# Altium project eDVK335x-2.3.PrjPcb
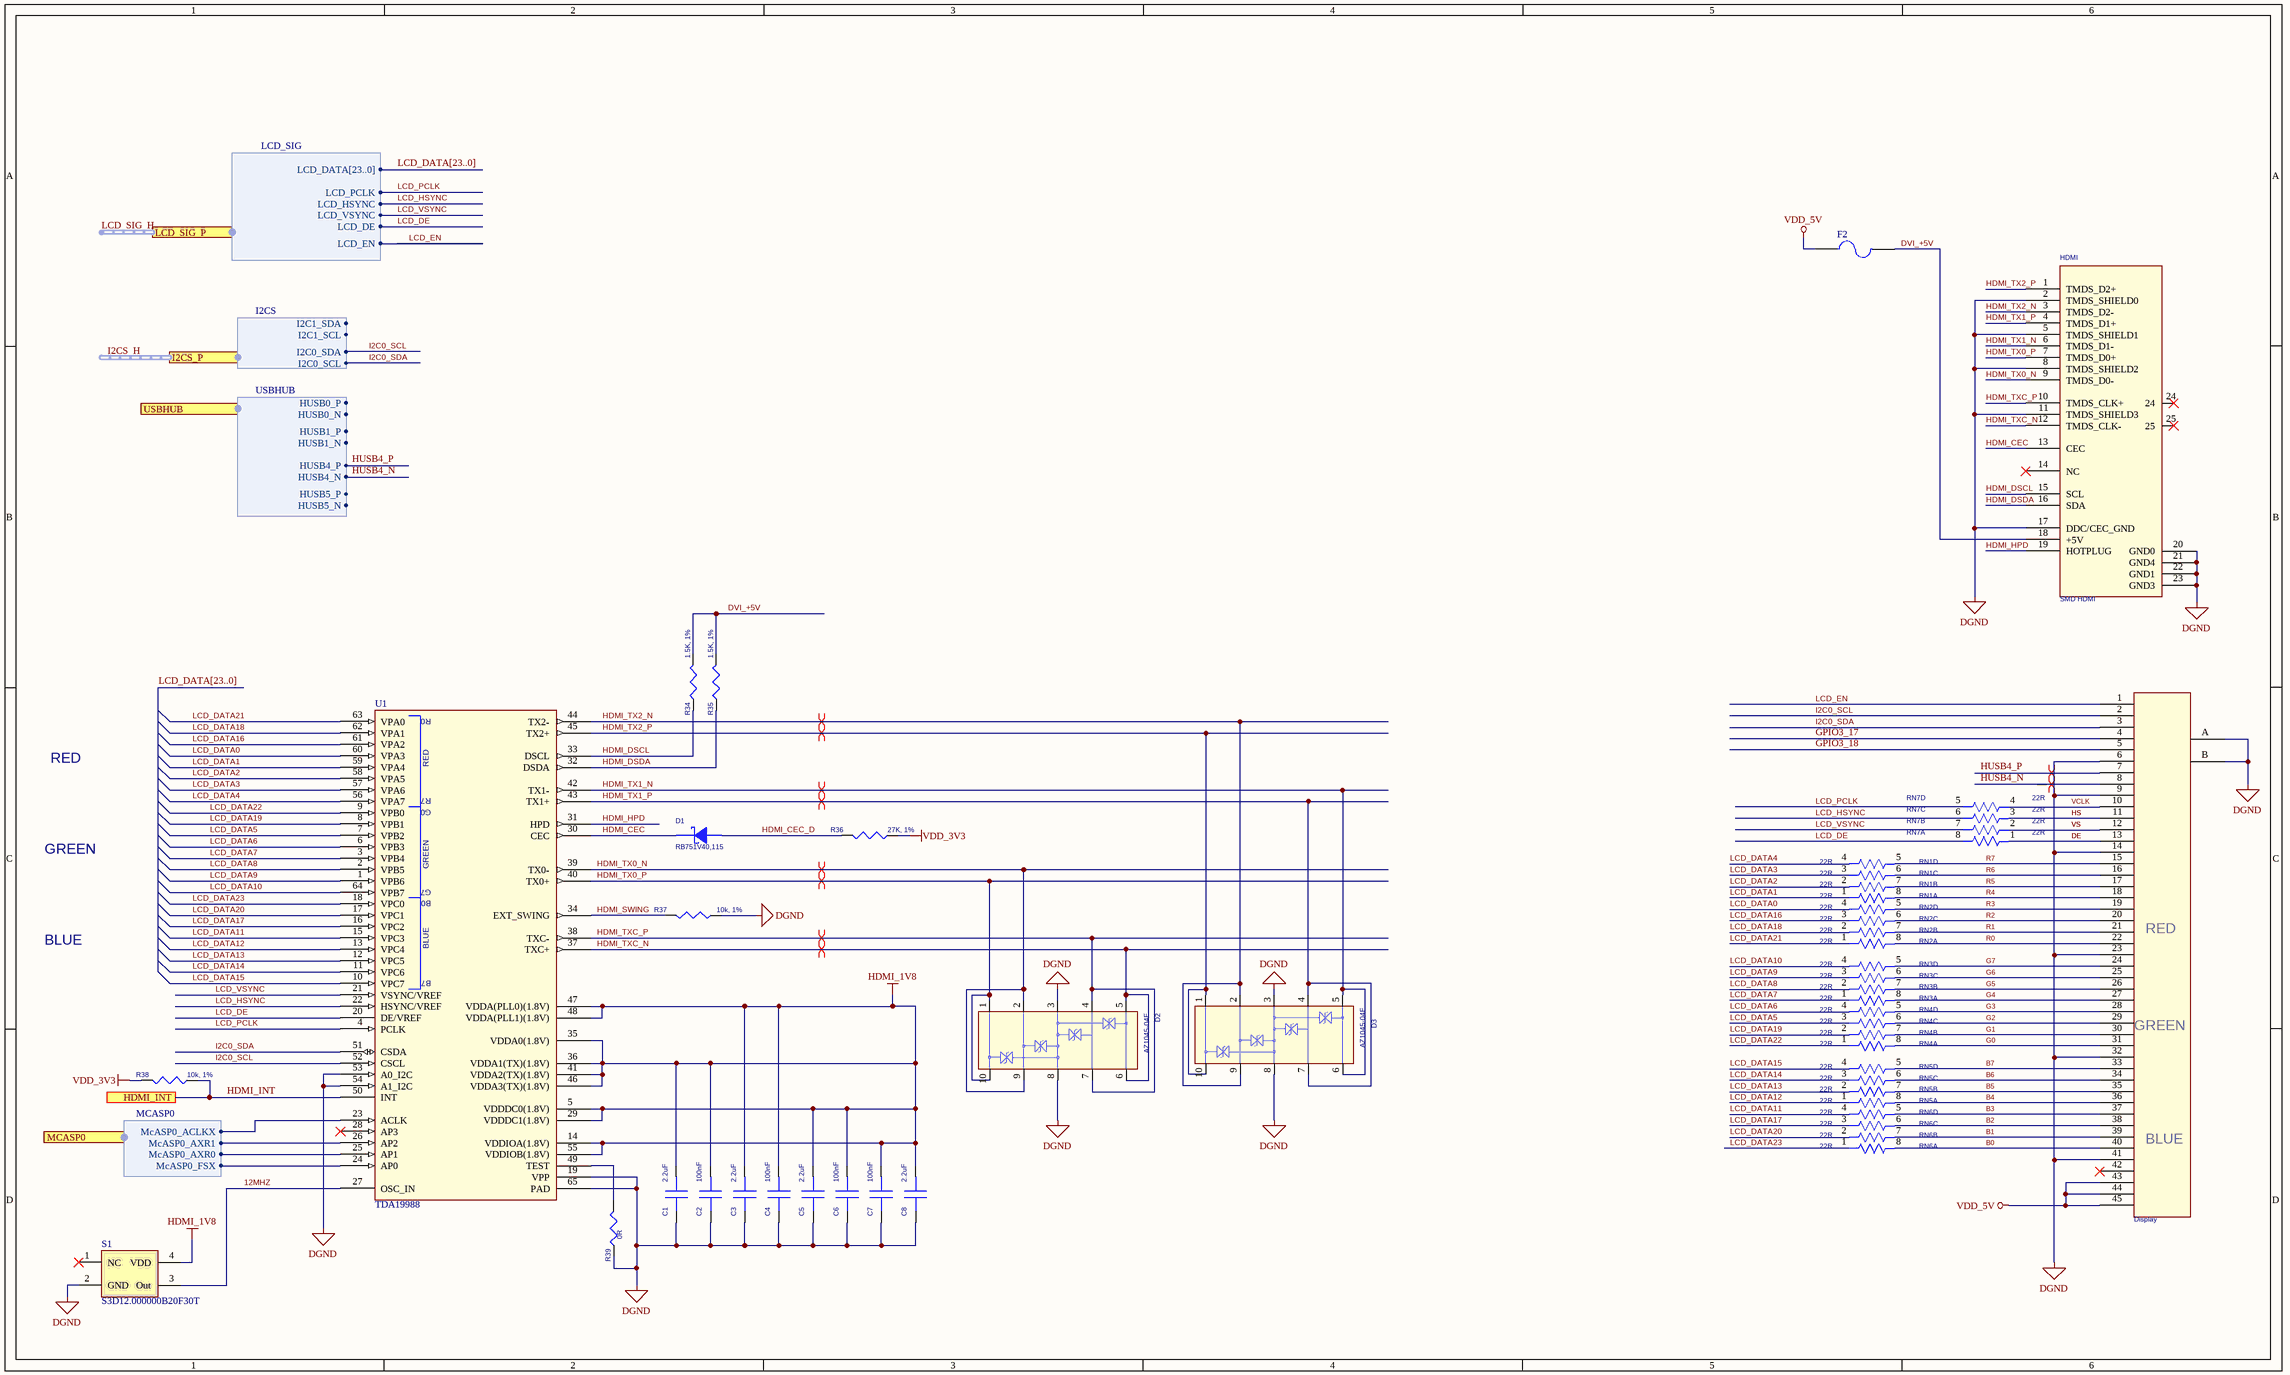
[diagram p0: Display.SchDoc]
13 sheets, 247 parts. Net scope: global (net labels, ports and power ports of the same name join across sheets).
Board file: eDVK335X-2.3.2.PcbDoc
Sheets:
  Display.SchDoc
  SODIMM-2.SchDoc
  mPCIUSB.SchDoc
  Eth.SchDoc
  Power.SchDoc
  SDCard.SchDoc
  Sound.SchDoc
  Config.SchDoc
  USBHUB2.SchDoc
  UARTS.SchDoc
  Others.SchDoc
  eMod-Wifi.SchDoc
  CAN.SchDoc

## Sheet Display.SchDoc
size 508 x 304 mm

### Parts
C1  2.2uF  [C0603]
C2  100nF  [C0603]
C3  2.2uF  [C0603]
C4  100nF  [C0603]
C5  2.2uF  [C0603]
C6  100nF  [C0603]
C7  100nF  [C0603]
C8  2.2uF  [C0603]
D1  RB751V40,115  [SOD323]
D2  AZ1045-04F  [DFN2510P10E]
D3  AZ1045-04F  [DFN2510P10E]
Display  FPC - 45  [con-fpc-p05-45p]  (value not drawn)
F2  Fuse 1A  [F1206]  (value not drawn)
HDMI  SMD HDMI  [HDMI0119-20-RM-A-SMD]
R34  1.5K, 1%  [R0603]
R35  1.5K, 1%  [R0603]
R36  27K, 1%  [R0603]
R37  10k, 1%  [R0603]
R38  10k, 1%  [R0603]
R39  0R  [R0603]
RN1  22R  [rn-8p4r-0603]  (parts A,B,C,D of 4)
RN2  22R  [rn-8p4r-0603]  (parts A,B,C,D of 4)
RN3  22R  [rn-8p4r-0603]  (parts A,B,C,D of 4)
RN4  22R  [rn-8p4r-0603]  (parts A,B,C,D of 4)
RN5  22R  [rn-8p4r-0603]  (parts A,B,C,D of 4)
RN6  22R  [rn-8p4r-0603]  (parts A,B,C,D of 4)
RN7  22R  [rn-8p4r-0603]  (parts A,B,C,D of 4)
S1  S3D12.000000B20F30T  [OSCSC250P320X250X100-4N-2]
U1  TDA19988  [QFN64S9X9P5]

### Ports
HDMI_INT, I2CS_P (harness I2CS), LCD_SIG_P (harness LCD_SIG), MCASP0 (harness MCASP0), USBHUB (harness USBHUB)

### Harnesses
MCASP0: McASP0_ACLKX, McASP0_FSX, McASP0_AXR0, McASP0_AXR1
LCD_SIG: LCD_DATA[23..0], LCD_PCLK, LCD_HSYNC, LCD_VSYNC, LCD_DE, LCD_EN
I2CS: I2C0_SDA, I2C0_SCL, I2C1_SDA, I2C1_SCL
USBHUB: HUSB0_P, HUSB0_N, HUSB1_P, HUSB1_N, HUSB4_P, HUSB4_N, HUSB5_P, HUSB5_N

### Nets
DGND: C1.2 C2.2 C3.2 C4.2 C5.2 C6.2 C7.2 C8.2 D2.3 D2.8 D3.3 D3.8 Display.6(VD3) Display.9(VD6) Display.14(VD10) Display.23(VD18) Display.32(nRESET) Display.41(NC4) Display.A Display.B HDMI.2(TMDS_SHIELD0) HDMI.5(TMDS_SHIELD1) HDMI.8(TMDS_SHIELD2) HDMI.11(TMDS_SHIELD3) HDMI.17(DDC/CEC_GND) HDMI.20(GND0) HDMI.21(GND4) HDMI.22(GND1) HDMI.23(GND3) R37.2(P2) R39.2(P2) S1.2(GND) U1.19(VPP) U1.53(A0_I2C) U1.54(A1_I2C) U1.65(PAD)
HDMI_1V8: C1.1 C2.1 C3.1 C4.1 C5.1 C6.1 C7.1 C8.1 S1.4(VDD) U1.5(VDDDC0(1.8V)) U1.14(VDDIOA(1.8V)) U1.29(VDDDC1(1.8V)) U1.35(VDDA0(1.8V)) U1.36(VDDA1(TX)(1.8V)) U1.41(VDDA2(TX)(1.8V)) U1.46(VDDA3(TX)(1.8V)) U1.47(VDDA(PLL0)(1.8V)) U1.48(VDDA(PLL1)(1.8V)) U1.55(VDDIOB(1.8V))
VDD_3V3: R36.2(P2) R38.1(P1)
VDD_5V: Display.43(NC3) Display.44(NC4) Display.45(NC4) F2.2
12MHZ: S1.3(Out) U1.27(OSC_IN)
B0: Display.40(NC4) RN6.8
B1: Display.39(NC3) RN6.7
B2: Display.38(NC2) RN6.6
B3: Display.37(NC1) RN6.5
B4: Display.36(VCLK) RN5.8
B5: Display.35(HSYNC) RN5.7
B6: Display.34(VSYNC) RN5.6
B7: Display.33(VDEN) RN5.5
DE: Display.13(VD9) RN7.1
DVI_+5V: F2.1 HDMI.18(+5V) R34.1(P1) R35.1(P1)
G0: Display.31(EINT10) RN4.8
G1: Display.30(TOUT1) RN4.7
G2: Display.29(GND3) RN4.6
G3: Display.28(VD23) RN4.5
G4: Display.27(VD22) RN3.8
G5: Display.26(VD21) RN3.7
G6: Display.25(VD20) RN3.6
G7: Display.24(VD19) RN3.5
GPIO3_17: Display.4(VD1)
GPIO3_18: Display.5(VD2)
HDMI_CEC: D1.1(C) HDMI.13(CEC) U1.30(CEC)
HDMI_CEC_D: D1.2(A) R36.1(P1)
HDMI_DSCL: HDMI.15(SCL) R34.2(P2) U1.33(DSCL)
HDMI_DSDA: HDMI.16(SDA) R35.2(P2) U1.32(DSDA)
HDMI_HPD: HDMI.19(HOTPLUG) U1.31(HPD)
HDMI_INT: R38.2(P2) U1.50(INT) ; port HDMI_INT
HDMI_SWING: R37.1(P1) U1.34(EXT_SWING)
HDMI_TX0_N: D2.2 D2.9 HDMI.9(TMDS_D0-) U1.39(TX0-)
HDMI_TX0_P: D2.1 D2.10 HDMI.7(TMDS_D0+) U1.40(TX0+)
HDMI_TX1_N: D3.5 D3.6 HDMI.6(TMDS_D1-) U1.42(TX1-)
HDMI_TX1_P: D3.4 D3.7 HDMI.4(TMDS_D1+) U1.43(TX1+)
HDMI_TX2_N: D3.2 D3.9 HDMI.3(TMDS_D2-) U1.44(TX2-)
HDMI_TX2_P: D3.1 D3.10 HDMI.1(TMDS_D2+) U1.45(TX2+)
HDMI_TXC_N: D2.5 D2.6 HDMI.12(TMDS_CLK-) U1.37(TXC+)
HDMI_TXC_P: D2.4 D2.7 HDMI.10(TMDS_CLK+) U1.38(TXC-)
HS: Display.11(GND1) RN7.3
HUSB4_N: Display.8(VD5) ; port USBHUB.HUSB4_N
HUSB4_P: Display.7(VD4) ; port USBHUB.HUSB4_P
I2C0_SCL: Display.2(VDD5V_2) Display.3(VD0) U1.51(CSDA) U1.52(CSCL) ; port I2CS_P.I2C0_SDA, port I2CS_P.I2C0_SCL  [also labelled I2C0_SDA]
LCD_DATA0: RN2.4 U1.60(VPA3)
LCD_DATA1: RN1.1 U1.59(VPA4)
LCD_DATA2: RN1.2 U1.58(VPA5)
LCD_DATA3: RN1.3 U1.57(VPA6)
LCD_DATA4: RN1.4 U1.56(VPA7)
LCD_DATA5: RN4.3 U1.7(VPB2)
LCD_DATA6: RN4.4 U1.6(VPB3)
LCD_DATA7: RN3.1 U1.3(VPB4)
LCD_DATA8: RN3.2 U1.2(VPB5)
LCD_DATA9: RN3.3 U1.1(VPB6)
LCD_DATA10: RN3.4 U1.64(VPB7)
LCD_DATA11: RN6.4 U1.15(VPC3)
LCD_DATA12: RN5.1 U1.13(VPC4)
LCD_DATA13: RN5.2 U1.12(VPC5)
LCD_DATA14: RN5.3 U1.11(VPC6)
LCD_DATA15: RN5.4 U1.10(VPC7)
LCD_DATA16: RN2.3 U1.61(VPA2)
LCD_DATA17: RN6.3 U1.16(VPC2)
LCD_DATA18: RN2.2 U1.62(VPA1)
LCD_DATA19: RN4.2 U1.8(VPB1)
LCD_DATA20: RN6.2 U1.17(VPC1)
LCD_DATA21: RN2.1 U1.63(VPA0)
LCD_DATA22: RN4.1 U1.9(VPB0)
LCD_DATA23: RN6.1 U1.18(VPC0)
LCD_DE: RN7.8 U1.20(DE/VREF) ; port LCD_SIG_P.LCD_DE
LCD_EN: Display.1(VDD5V_1) ; port LCD_SIG_P.LCD_EN
LCD_HSYNC: RN7.6 U1.22(HSYNC/VREF) ; port LCD_SIG_P.LCD_HSYNC
LCD_PCLK: RN7.5 U1.4(PCLK) ; port LCD_SIG_P.LCD_PCLK
LCD_VSYNC: RN7.7 U1.21(VSYNC/VREF) ; port LCD_SIG_P.LCD_VSYNC  [project net LCD_SIG_H.LCD_VSYNC]
McASP0_ACLKX: U1.23(ACLK) ; port MCASP0.McASP0_ACLKX
McASP0_AXR0: U1.25(AP1) ; port MCASP0.McASP0_AXR0
McASP0_AXR1: U1.26(AP2) ; port MCASP0.McASP0_AXR1
McASP0_FSX: U1.24(AP0) ; port MCASP0.McASP0_FSX
R0: Display.22(VD17) RN2.8
R1: Display.21(VD16) RN2.7
R2: Display.20(GND2) RN2.6
R3: Display.19(VD15) RN2.5
R4: Display.18(VD14) RN1.8
R5: Display.17(VD13) RN1.7
R6: Display.16(VD12) RN1.6
R7: Display.15(VD11) RN1.5
VCLK: Display.10(VD7) RN7.4
VS: Display.12(VD8) RN7.2
NetR39_1: R39.1(P1) U1.49(TEST)

Not connected (* = marked no-connect by the designer): Display 42(NC2)*; HDMI 14(NC)* 24* 25*; S1 1(NC)*; U1 28(AP3)*

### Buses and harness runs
bus LCD_DATA[23..0]
harness I2CS_H = port I2CS_P
harness LCD_SIG_H = port LCD_SIG_P

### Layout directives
differential pair: HDMI_TX0_N, HDMI_TX0_P, HDMI_TX1_N, HDMI_TX1_P, HDMI_TX2_N, HDMI_TX2_P, HDMI_TXC_N, HDMI_TXC_P, HUSB4_N, HUSB4_P

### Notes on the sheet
- RED
- GREEN
- (near Display) RED
- BLUE
- (near Display) GREEN
- (near Display) BLUE

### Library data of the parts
C1 C3 C5 C8 = CAP SMD: CAP CER 2.2UF 6.3V 10% X5R 0402; Manufacturer: TDK Corporation; Manufacturer Part Number: C1005X5R0J225K050BC; Capacitance: 2.2µF
C2 C4 C6 C7 = CAP SMD: CAP CER 0.1UF 6.3V 10% X5R 0402; Manufacturer: TDK Corporation; Manufacturer Part Number: C1005X5R0J104K050BA; Capacitance: 0.1µF
D1 = Zener: DIODE SCHOTTKY 40V 120MA SOD323; Manufacturer: NXP Semiconductors; Current - Average Rectified (Io): 120mA (DC); Voltage - Forward (Vf) (Max) @ If: 370mV @ 1mA; Speed: Small Signal =< 200mA (Io), Any Speed; Current - Reverse Leakage @ Vr: 500nA @ 30V; Capacitance @ Vr, F: 2pF @ 1V, 1MHz
D2 D3 = TVS Arrays_1
Display = LCD-888_0: FPC, 45pin, 0.5mm pitch, Bottom Contact, Flip Lock
F2 = Fuse 2: Fuse 1A (1206)
HDMI = HDMI_2
R34 R35 = RES SMD: Manufacturer: Yageo; Manufacturer Part Number: RC0402FR-071K5L; Power (Watts): 0.063W, 1/16W; Temperature Coefficient: ±100ppm/°C
R36 = RES SMD: RES 27.0K OHM 1/16W 1% 0402 SMD; Manufacturer: Yageo; Manufacturer Part Number: RC0402FR-0727KL; Power (Watts): 0.063W, 1/16W; Temperature Coefficient: ±100ppm/°C
R37 R38 = RES SMD: RES 10K OHM 1/16W 5% 0402 SMD; Manufacturer: Rohm Semiconductor; Manufacturer Part Number: MCR01MZPJ103; Power (Watts): 0.063W, 1/16W; Temperature Coefficient: ±200ppm/°C
R39 = RES SMD: Manufacturer: Yageo; Manufacturer Part Number: RC0402JR-070RL; Resistance (Ohms): 0.0; Power (Watts): 0.063W, 1/16W; Tolerance: Jumper
RN1-RN7 = R_PAK4: ?; OriginalSymbolOrigin: (-100,50)
S1 = ABM8G_1: OSC; SMD; 4 Leads; Body 3.2 x 2.5  P.N: S3D24.576000D20F30T; Manufacturer: TXC; Manufacturer PN: 7V; Designator: ABM8G
U1 = TDA19988: IC HDMI TRANSMITTER 64-HVQFN; Manufacturer: NXP Semiconductors; Manufacturer Part Number: TDA19988AHN/C1,551

## Sheet SODIMM-2.SchDoc
size A2
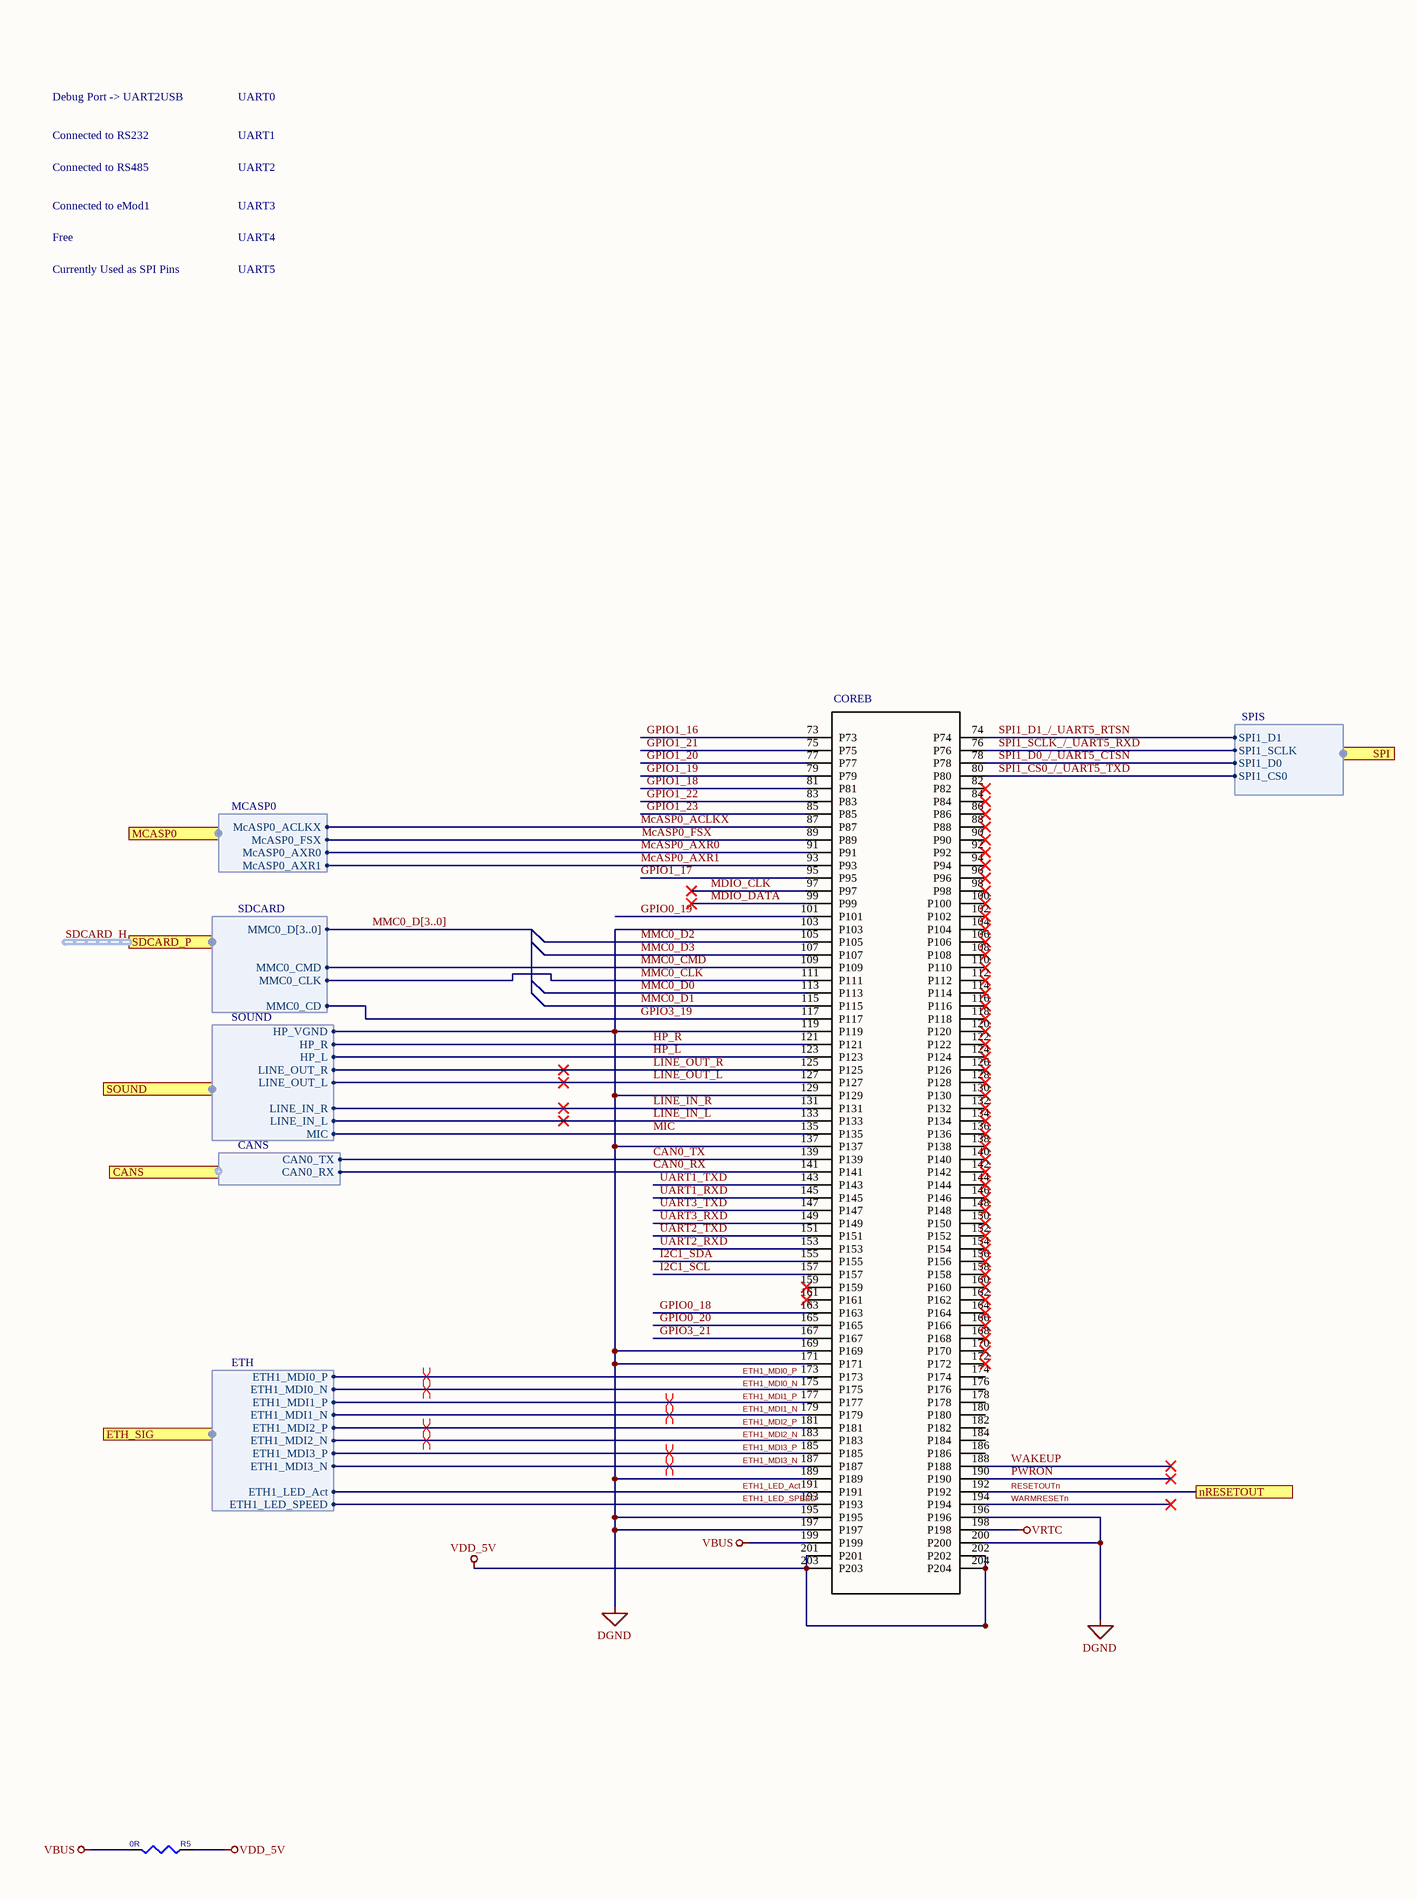
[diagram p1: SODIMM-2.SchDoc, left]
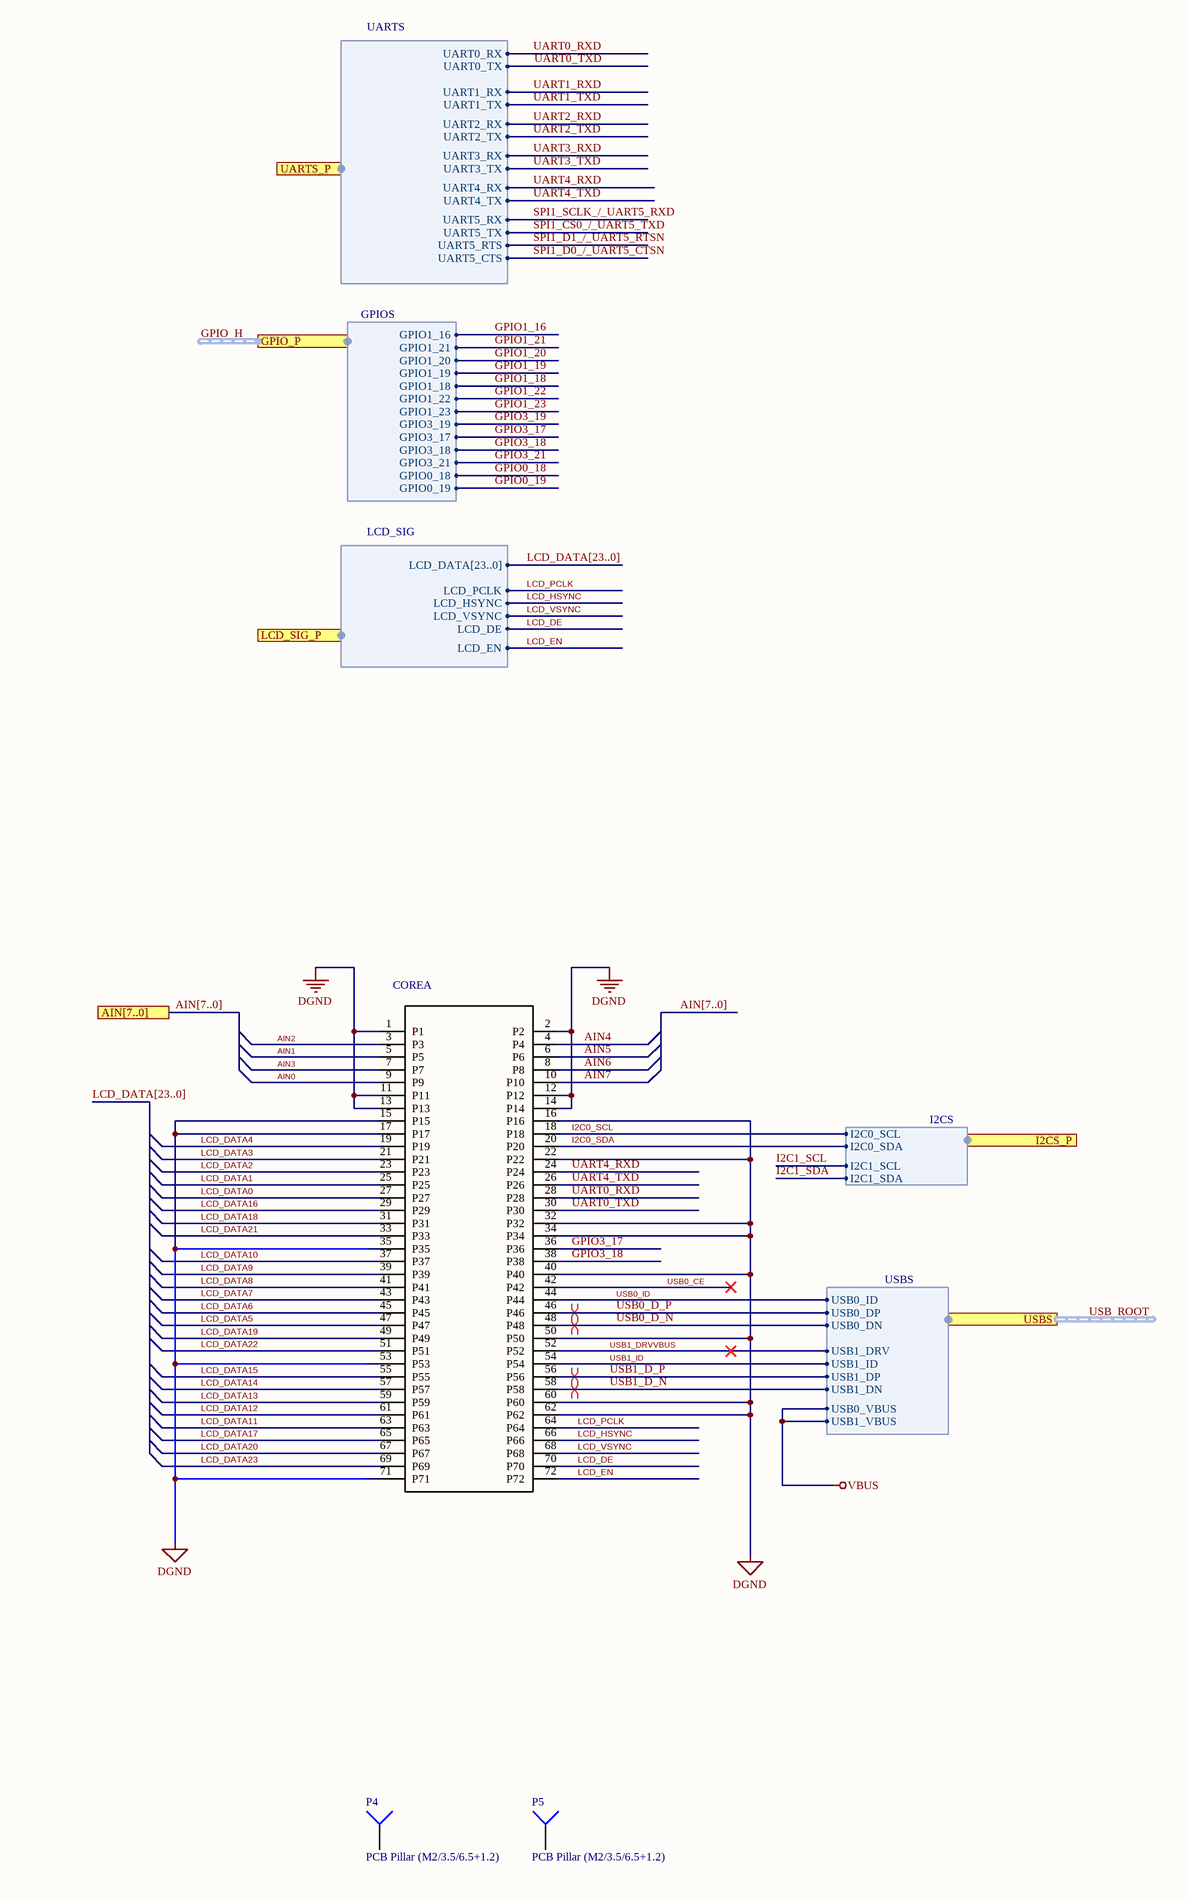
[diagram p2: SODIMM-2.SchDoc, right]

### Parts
CORE  SODIMM-204  [TE_2-2013289-1]  (value not drawn)  (parts A,B of 2)
P4  PCB Pillar (M2/3.5/6.5+1.2)  [PCB Pillar]
P5  PCB Pillar (M2/3.5/6.5+1.2)  [PCB Pillar]
R5  0R  [R0603]

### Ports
AIN[7..0], CANS (harness CANS), ETH_SIG (harness ETH), GPIO_P (harness GPIOS), I2CS_P (harness I2CS), LCD_SIG_P (harness LCD_SIG), MCASP0 (harness MCASP0), nRESETOUT, SDCARD_P (harness SDCARD), SOUND (harness SOUND), SPI (harness SPIS), UARTS_P (harness UARTS), USBS (harness USBS)

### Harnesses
ETH: ETH1_MDI0_P, ETH1_MDI0_N, ETH1_MDI1_P, ETH1_MDI1_N, ETH1_MDI2_P, ETH1_MDI2_N, ETH1_MDI3_P, ETH1_MDI3_N, ETH1_LED_Act, ETH1_LED_SPEED
SDCARD: MMC0_CLK, MMC0_CMD, MMC0_D[3..0], MMC0_CD
MCASP0: McASP0_ACLKX, McASP0_FSX, McASP0_AXR0, McASP0_AXR1
LCD_SIG: LCD_DATA[23..0], LCD_PCLK, LCD_HSYNC, LCD_VSYNC, LCD_DE, LCD_EN
UARTS: UART0_RX, UART0_TX, UART1_RX, UART1_TX, UART2_RX, UART2_TX, UART3_RX, UART3_TX, UART4_RX, UART4_TX, UART5_RX, UART5_TX, UART5_RTS, UART5_CTS
SOUND: HP_R, HP_L, HP_VGND, LINE_OUT_R, LINE_OUT_L, LINE_IN_R, LINE_IN_L, MIC
CANS: CAN0_TX, CAN0_RX
I2CS: I2C0_SDA, I2C0_SCL, I2C1_SDA, I2C1_SCL
SPIS: SPI1_SCLK, SPI1_D0, SPI1_D1, SPI1_CS0
GPIOS: GPIO1_16, GPIO1_21, GPIO1_20, GPIO1_19, GPIO1_18, GPIO1_22, GPIO1_23, GPIO3_19, GPIO3_17, GPIO3_18, GPIO3_21, GPIO0_18, GPIO0_19
USBS: USB0_ID, USB0_VBUS, USB0_DP, USB0_DN, USB1_ID, USB1_VBUS, USB1_DP, USB1_DN, USB1_DRV

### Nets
DGND: CORE.1(P1) CORE.2(P2) CORE.11(P11) CORE.12(P12) CORE.13(P13) CORE.14(P14) CORE.15(P15) CORE.16(P16) CORE.17(P17) CORE.22(P22) CORE.32(P32) CORE.34(P34) CORE.35(P35) CORE.40(P40) CORE.50(P50) CORE.53(P53) CORE.60(P60) CORE.62(P62) CORE.71(P71) CORE.103(P103) CORE.119(P119) CORE.129(P129) CORE.137(P137) CORE.169(P169) CORE.171(P171) CORE.189(P189) CORE.195(P195) CORE.196(P196) CORE.197(P197) CORE.200(P200) ; port SOUND.HP_VGND
VBUS: CORE.199(P199) R5.2 ; harness USBS.USB0_VBUS, harness USBS.USB1_VBUS
VDD_5V: CORE.201(P201) CORE.202(P202) CORE.203(P203) CORE.204(P204) R5.1
VRTC: CORE.198(P198)
AIN0: CORE.9(P9)
AIN1: CORE.5(P5)
AIN2: CORE.3(P3)
AIN3: CORE.7(P7)
AIN4: CORE.4(P4)
AIN5: CORE.6(P6)
AIN6: CORE.8(P8)
AIN7: CORE.10(P10)
CAN0_RX: CORE.141(P141) ; port CANS.CAN0_RX
CAN0_TX: CORE.139(P139) ; port CANS.CAN0_TX
ETH1_LED_Act: CORE.191(P191) ; port ETH_SIG.ETH1_LED_Act
ETH1_LED_SPEED: CORE.193(P193) ; port ETH_SIG.ETH1_LED_SPEED
ETH1_MDI0_N: CORE.175(P175) ; port ETH_SIG.ETH1_MDI0_N
ETH1_MDI0_P: CORE.173(P173) ; port ETH_SIG.ETH1_MDI0_P
ETH1_MDI1_N: CORE.179(P179) ; port ETH_SIG.ETH1_MDI1_N
ETH1_MDI1_P: CORE.177(P177) ; port ETH_SIG.ETH1_MDI1_P
ETH1_MDI2_N: CORE.183(P183) ; port ETH_SIG.ETH1_MDI2_N
ETH1_MDI2_P: CORE.181(P181) ; port ETH_SIG.ETH1_MDI2_P
ETH1_MDI3_N: CORE.187(P187) ; port ETH_SIG.ETH1_MDI3_N
ETH1_MDI3_P: CORE.185(P185) ; port ETH_SIG.ETH1_MDI3_P
GPIO0_18: CORE.163(P163) ; port GPIO_P.GPIO0_18
GPIO0_19: CORE.101(P101) ; port GPIO_P.GPIO0_19
GPIO0_20: CORE.165(P165)
GPIO1_16: CORE.73(P73) ; port GPIO_P.GPIO1_16
GPIO1_17: CORE.95(P95)
GPIO1_18: CORE.81(P81) ; port GPIO_P.GPIO1_18
GPIO1_19: CORE.79(P79) ; port GPIO_P.GPIO1_19
GPIO1_20: CORE.77(P77) ; port GPIO_P.GPIO1_20
GPIO1_21: CORE.75(P75) ; port GPIO_P.GPIO1_21
GPIO1_22: CORE.83(P83) ; port GPIO_P.GPIO1_22
GPIO1_23: CORE.85(P85) ; port GPIO_P.GPIO1_23
GPIO3_17: CORE.36(P36) ; port GPIO_P.GPIO3_17
GPIO3_18: CORE.38(P38) ; port GPIO_P.GPIO3_18
GPIO3_19: CORE.117(P117) ; port SDCARD_P.MMC0_CD, port GPIO_P.GPIO3_19
GPIO3_21: CORE.167(P167) ; port GPIO_P.GPIO3_21
HP_L: CORE.123(P123) ; port SOUND.HP_L  [project net HP-L]
HP_R: CORE.121(P121) ; port SOUND.HP_R  [project net HP-R]
I2C0_SCL: CORE.18(P18) CORE.20(P20) ; port I2CS_P.I2C0_SDA, port I2CS_P.I2C0_SCL  [also labelled I2C0_SDA]
I2C1_SCL: CORE.157(P157) ; port I2CS_P.I2C1_SCL
I2C1_SDA: CORE.155(P155) ; port I2CS_P.I2C1_SDA
LCD_DATA0: CORE.27(P27)
LCD_DATA1: CORE.25(P25)
LCD_DATA2: CORE.23(P23)
LCD_DATA3: CORE.21(P21)
LCD_DATA4: CORE.19(P19)
LCD_DATA5: CORE.47(P47)
LCD_DATA6: CORE.45(P45)
LCD_DATA7: CORE.43(P43)
LCD_DATA8: CORE.41(P41)
LCD_DATA9: CORE.39(P39)
LCD_DATA10: CORE.37(P37)
LCD_DATA11: CORE.63(P63)
LCD_DATA12: CORE.61(P61)
LCD_DATA13: CORE.59(P59)
LCD_DATA14: CORE.57(P57)
LCD_DATA15: CORE.55(P55)
LCD_DATA16: CORE.29(P29)
LCD_DATA17: CORE.65(P65)
LCD_DATA18: CORE.31(P31)
LCD_DATA19: CORE.49(P49)
LCD_DATA20: CORE.67(P67)
LCD_DATA21: CORE.33(P33)
LCD_DATA22: CORE.51(P51)
LCD_DATA23: CORE.69(P69)
LCD_DE: CORE.70(P70) ; port LCD_SIG_P.LCD_DE
LCD_EN: CORE.72(P72) ; port LCD_SIG_P.LCD_EN
LCD_HSYNC: CORE.66(P66) ; port LCD_SIG_P.LCD_HSYNC
LCD_PCLK: CORE.64(P64) ; port LCD_SIG_P.LCD_PCLK
LCD_VSYNC: CORE.68(P68) ; port LCD_SIG_P.LCD_VSYNC  [project net LCD_SIG_H.LCD_VSYNC]
LINE_IN_L: CORE.133(P133) ; port SOUND.LINE_IN_L
LINE_IN_R: CORE.131(P131) ; port SOUND.LINE_IN_R
LINE_OUT_L: CORE.127(P127) ; port SOUND.LINE_OUT_L
LINE_OUT_R: CORE.125(P125) ; port SOUND.LINE_OUT_R
McASP0_ACLKX: CORE.87(P87) ; port MCASP0.McASP0_ACLKX
McASP0_AXR0: CORE.91(P91) ; port MCASP0.McASP0_AXR0
McASP0_AXR1: CORE.93(P93) ; port MCASP0.McASP0_AXR1
McASP0_FSX: CORE.89(P89) ; port MCASP0.McASP0_FSX
MDIO_CLK: CORE.97(P97)
MDIO_DATA: CORE.99(P99)
MIC: CORE.135(P135) ; port SOUND.MIC
MMC0_CLK: CORE.111(P111) ; port SDCARD_P.MMC0_CLK
MMC0_CMD: CORE.109(P109) ; port SDCARD_P.MMC0_CMD
MMC0_D0: CORE.113(P113)
MMC0_D1: CORE.115(P115)
MMC0_D2: CORE.105(P105)
MMC0_D3: CORE.107(P107)
PWRON: CORE.190(P190)
RESETOUTn: CORE.192(P192) ; port nRESETOUT
SPI1_CS0_/_UART5_TXD: CORE.80(P80) ; port UARTS_P.UART5_TX, port SPI.SPI1_CS0
SPI1_D0_/_UART5_CTSN: CORE.78(P78) ; port UARTS_P.UART5_CTS, port SPI.SPI1_D0
SPI1_D1_/_UART5_RTSN: CORE.74(P74) ; port UARTS_P.UART5_RTS, port SPI.SPI1_D1
SPI1_SCLK_/_UART5_RXD: CORE.76(P76) ; port UARTS_P.UART5_RX, port SPI.SPI1_SCLK
UART0_RXD: CORE.28(P28) ; port UARTS_P.UART0_RX
UART0_TXD: CORE.30(P30) ; port UARTS_P.UART0_TX
UART1_RXD: CORE.145(P145) ; port UARTS_P.UART1_RX
UART1_TXD: CORE.143(P143) ; port UARTS_P.UART1_TX
UART2_RXD: CORE.153(P153) ; port UARTS_P.UART2_RX
UART2_TXD: CORE.151(P151) ; port UARTS_P.UART2_TX
UART3_RXD: CORE.149(P149) ; port UARTS_P.UART3_RX
UART3_TXD: CORE.147(P147) ; port UARTS_P.UART3_TX
UART4_RXD: CORE.24(P24) ; port UARTS_P.UART4_RX
UART4_TXD: CORE.26(P26) ; port UARTS_P.UART4_TX
USB0_CE: CORE.42(P42)
USB0_D_N: CORE.48(P48) ; harness USBS.USB0_DN
USB0_D_P: CORE.46(P46) ; harness USBS.USB0_DP
USB0_ID: CORE.44(P44) ; harness USBS.USB0_ID
USB1_D_N: CORE.58(P58) ; harness USBS.USB1_DN
USB1_D_P: CORE.56(P56) ; harness USBS.USB1_DP
USB1_DRVVBUS: CORE.52(P52) ; harness USBS.USB1_DRV
USB1_ID: CORE.54(P54) ; harness USBS.USB1_ID
WAKEUP: CORE.188(P188)
WARMRESETn: CORE.194(P194)

Not connected (* = marked no-connect by the designer): CORE 82(P82)* 84(P84)* 86(P86)* 88(P88)* 90(P90)* 92(P92)* 94(P94)* 96(P96)* 98(P98)* 100(P100)* 102(P102)* 104(P104)* 106(P106)* 108(P108)* 110(P110)* 112(P112)* 114(P114)* 116(P116)* 118(P118)* 120(P120)* 122(P122)* 124(P124)* 126(P126)* 128(P128)* 130(P130)* 132(P132)* 134(P134)* 136(P136)* 138(P138)* 140(P140)* 142(P142)* 144(P144)* 146(P146)* 148(P148)* 150(P150)* 152(P152)* 154(P154)* 156(P156)* 158(P158)* 159(P159)* 160(P160)* 161(P161)* 162(P162)* 164(P164)* 166(P166)* 168(P168)* 170(P170)* 172(P172)* 174(P174) 176(P176) 178(P178) 180(P180) 182(P182) 184(P184) 186(P186); P4 1; P5 1

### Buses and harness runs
bus AIN[7..0]
bus AIN[7..0] = port AIN[7..0]
bus LCD_DATA[23..0]
bus MMC0_D[3..0]
harness GPIO_H = port GPIO_P
harness SDCARD_H = port SDCARD_P
harness USB_ROOT = port USBS

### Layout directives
differential pair: ETH1_MDI0_N, ETH1_MDI0_P, ETH1_MDI1_N, ETH1_MDI1_P, ETH1_MDI2_N, ETH1_MDI2_P, ETH1_MDI3_N, ETH1_MDI3_P, USB0_D_N, USB0_D_P, USB1_D_N, USB1_D_P

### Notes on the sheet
- Debug Port -> UART2USB
- UART0
- Connected to RS232
- Connected to RS485
- UART1
- UART2
- Connected to eMod1
- Free
- UART3
- UART4
- Currently Used as SPI Pins
- UART5

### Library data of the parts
CORE = SODIMM-204: FOXCONN DDR3 204P 9.2H STD; Centerline_Pitch: .6 mm[.024 in]; MP: 2-2013289-1; Product_Type: Socket; MF: TE Connectivity; Number_of_Positions: 204
P4 P5 = Socket
R5 = R

## Sheet mPCIUSB.SchDoc
size 381 x 152 mm; SheetNumber: 8
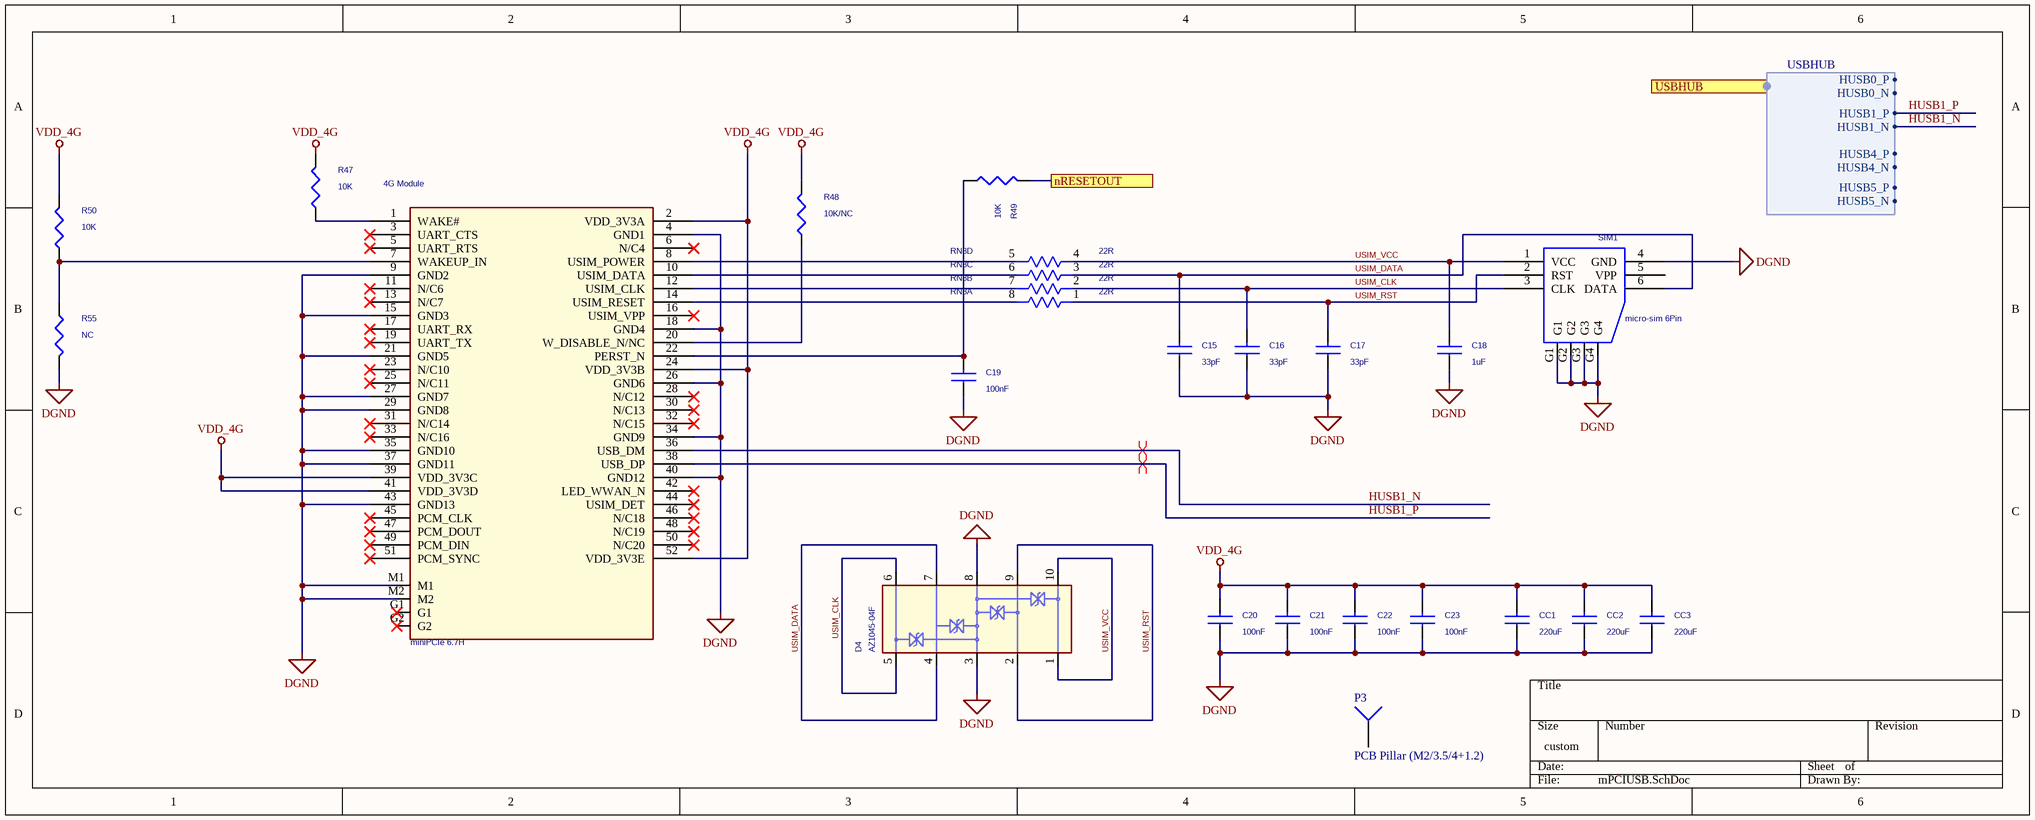
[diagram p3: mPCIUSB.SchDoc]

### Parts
4G_Module  miniPCIe 6.7H  [MINI_PCIEX1-52P-2h-2]
C15  33pF  [C0603]
C16  33pF  [C0603]
C17  33pF  [C0603]
C18  1uF  [C0603]
C19  100nF  [C0603]
C20  100nF  [C0603]
C21  100nF  [C0603]
C22  100nF  [C0603]
C23  100nF  [C0603]
CC1  220uF  [C1210]
CC2  220uF  [C1210]
CC3  220uF  [C1210]
D4  AZ1045-04F  [DFN2510P10E]
P3  PCB Pillar (M2/3.5/4+1.2)  [PCB Pillar]
R47  10K  [R0603]
R48  10K/NC  [R0603]
R49  10K  [R0603]
R50  10K  [R0603]
R55  NC  [R0603]
RN8  22R  [rn-8p4r-0603]  (parts A,B,C,D of 4)
SIM1  micro-sim 6Pin  [micro-sim]

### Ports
nRESETOUT, USBHUB (harness USBHUB)

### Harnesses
USBHUB: HUSB0_P, HUSB0_N, HUSB1_P, HUSB1_N, HUSB4_P, HUSB4_N, HUSB5_P, HUSB5_N

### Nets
DGND: 4G_Module.4(GND1) 4G_Module.9(GND2) 4G_Module.15(GND3) 4G_Module.18(GND4) 4G_Module.21(GND5) 4G_Module.26(GND6) 4G_Module.27(GND7) 4G_Module.29(GND8) 4G_Module.34(GND9) 4G_Module.35(GND10) 4G_Module.37(GND11) 4G_Module.40(GND12) 4G_Module.43(GND13) 4G_Module.M1 4G_Module.M2 C15.1 C16.1 C17.1 C18.1 C19.1 C20.1 C21.1 C22.1 C23.1 CC1.1 CC2.1 CC3.1 D4.3 D4.8 R55.2 SIM1.4(GND) SIM1.G1 SIM1.G2 SIM1.G3 SIM1.G4
VDD_4G: 4G_Module.2(VDD_3V3A) 4G_Module.24(VDD_3V3B) 4G_Module.39(VDD_3V3C) 4G_Module.41(VDD_3V3D) 4G_Module.52(VDD_3V3E) C20.2 C21.2 C22.2 C23.2 CC1.2 CC2.2 CC3.2 R47.2 R48.2 R50.2
HUSB1_N: 4G_Module.36(USB_DM) ; port USBHUB.HUSB1_N
HUSB1_P: 4G_Module.38(USB_DP) ; port USBHUB.HUSB1_P
RESETOUTn: R49.2 ; port nRESETOUT
USIM_CLK: C16.2 D4.5 D4.6 RN8.2 SIM1.3(CLK)
USIM_DATA: C15.2 D4.4 D4.7 RN8.3 SIM1.6(DATA)
USIM_RST: C17.2 D4.2 D4.9 RN8.1 SIM1.2(RST)
USIM_VCC: C18.2 D4.1 D4.10 RN8.4 SIM1.1(VCC)
Net4G_Module_1: 4G_Module.1(WAKE#) R47.1
Net4G_Module_7: 4G_Module.7(WAKEUP_IN) R50.1 R55.1
Net4G_Module_8: 4G_Module.8(USIM_POWER) RN8.5
Net4G_Module_10: 4G_Module.10(USIM_DATA) RN8.6
Net4G_Module_12: 4G_Module.12(USIM_CLK) RN8.7
Net4G_Module_14: 4G_Module.14(USIM_RESET) RN8.8
Net4G_Module_20: 4G_Module.20(W_DISABLE_N/NC) R48.1
Net4G_Module_22: 4G_Module.22(PERST_N) C19.2 R49.1

Not connected (* = marked no-connect by the designer): 4G_Module 3(UART_CTS)* 5(UART_RTS)* 6(N/C4)* 11(N/C6)* 13(N/C7)* 16(USIM_VPP)* 17(UART_RX)* 19(UART_TX)* 23(N/C10)* 25(N/C11)* 28(N/C12)* 30(N/C13)* 31(N/C14)* 32(N/C15)* 33(N/C16)* 42(LED_WWAN_N)* 44(USIM_DET)* 45(PCM_CLK)* 46(N/C18)* 47(PCM_DOUT)* 48(N/C19)* 49(PCM_DIN)* 50(N/C20)* 51(PCM_SYNC)* G1* G2*; P3 1; SIM1 5(VPP)

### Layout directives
differential pair: HUSB1_N, HUSB1_P

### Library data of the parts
4G_Module = CON50A_2
C15-C23 CC1-CC3 = CAP NP
D4 = TVS Arrays_1
P3 = Socket
R47-R50 R55 = R
RN8 = R_PAK4: OriginalSymbolOrigin: (-100,50)
SIM1 = SIMCARD_1

## Sheet Eth.SchDoc
size 254 x 127 mm; SheetNumber: 6
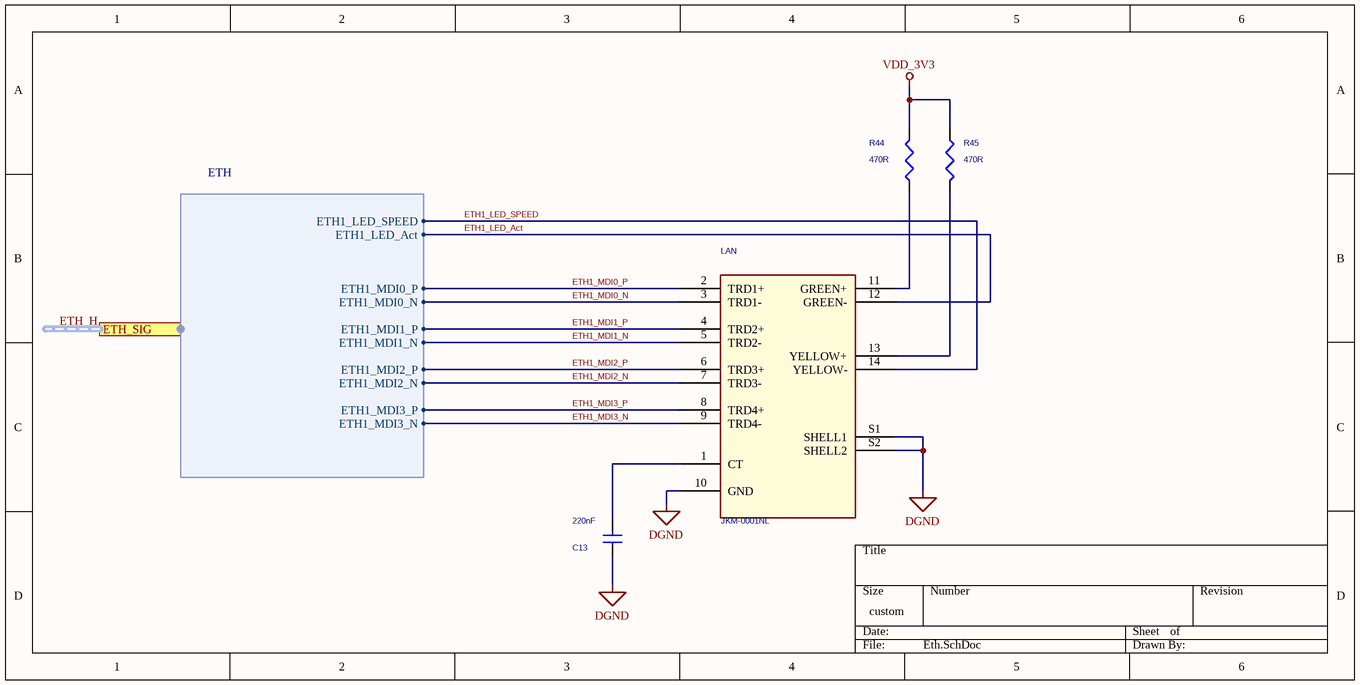
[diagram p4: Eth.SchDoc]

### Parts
C13  220nF  [C0603]
LAN  JKM-0001NL  [LPJG0820GENL]
R44  470R  [R0603]
R45  470R  [R0603]

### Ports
ETH_SIG (harness ETH)

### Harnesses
ETH: ETH1_MDI0_P, ETH1_MDI0_N, ETH1_MDI1_P, ETH1_MDI1_N, ETH1_MDI2_P, ETH1_MDI2_N, ETH1_MDI3_P, ETH1_MDI3_N, ETH1_LED_Act, ETH1_LED_SPEED

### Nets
DGND: C13.1 LAN.10(GND) LAN.S1(SHELL1) LAN.S2(SHELL2)
VDD_3V3: R44.1 R45.2
ETH1_LED_Act: LAN.12(GREEN-) ; port ETH_SIG.ETH1_LED_Act
ETH1_LED_SPEED: LAN.14(YELLOW-) ; port ETH_SIG.ETH1_LED_SPEED
ETH1_MDI0_N: LAN.3(TRD1-) ; port ETH_SIG.ETH1_MDI0_N
ETH1_MDI0_P: LAN.2(TRD1+) ; port ETH_SIG.ETH1_MDI0_P
ETH1_MDI1_N: LAN.5(TRD2-) ; port ETH_SIG.ETH1_MDI1_N
ETH1_MDI1_P: LAN.4(TRD2+) ; port ETH_SIG.ETH1_MDI1_P
ETH1_MDI2_N: LAN.7(TRD3-) ; port ETH_SIG.ETH1_MDI2_N
ETH1_MDI2_P: LAN.6(TRD3+) ; port ETH_SIG.ETH1_MDI2_P
ETH1_MDI3_N: LAN.9(TRD4-) ; port ETH_SIG.ETH1_MDI3_N
ETH1_MDI3_P: LAN.8(TRD4+) ; port ETH_SIG.ETH1_MDI3_P
NetC13_2: C13.2 LAN.1(CT)
NetLAN_11: LAN.11(GREEN+) R44.2
NetLAN_13: LAN.13(YELLOW+) R45.1

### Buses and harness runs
harness ETH_H = port ETH_SIG

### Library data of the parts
C13 = CAP
LAN = CON10_1
R44 R45 = RES

## Sheet Power.SchDoc
size 558 x 177 mm
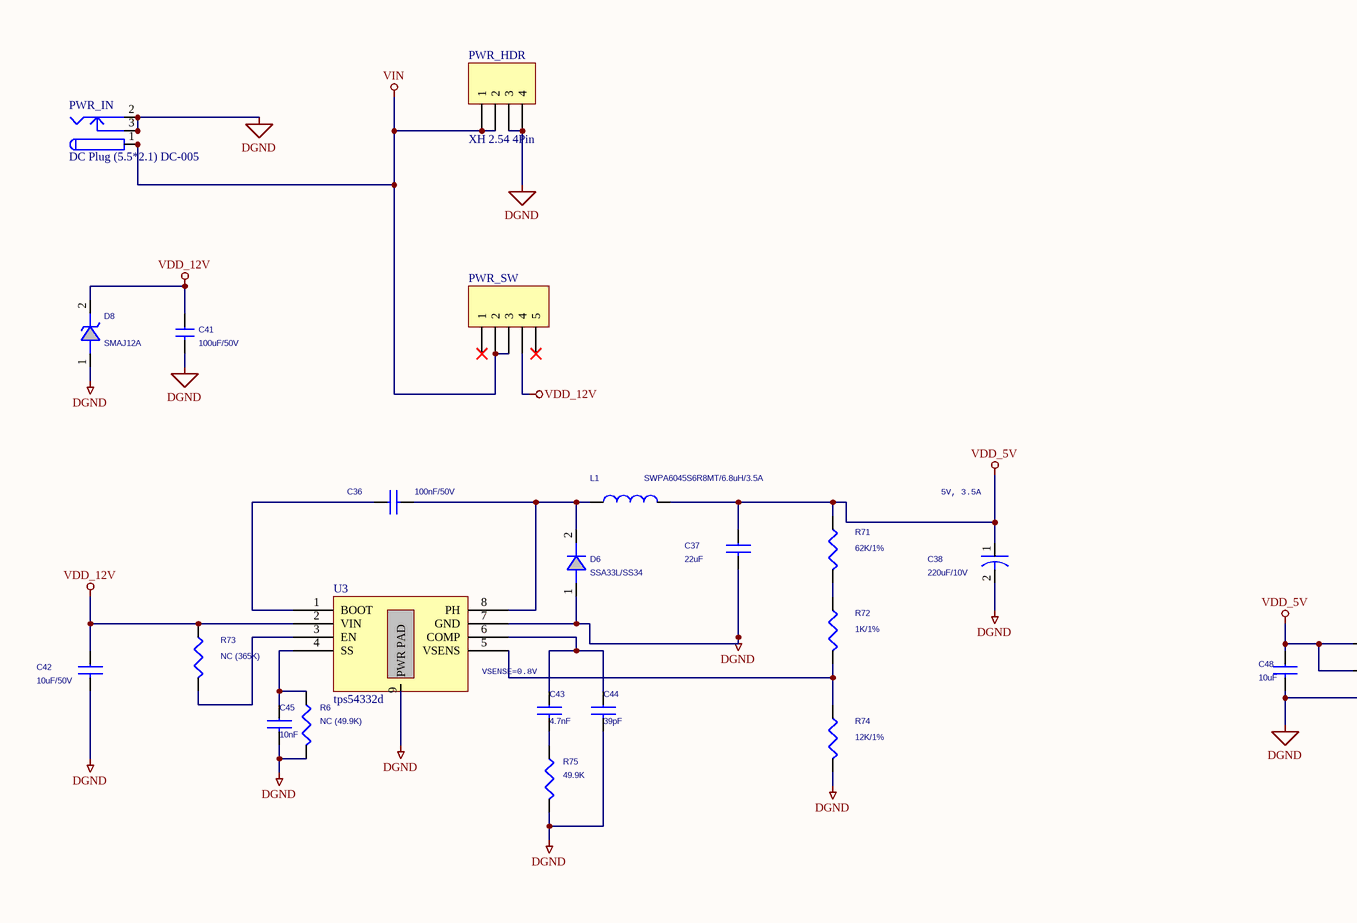
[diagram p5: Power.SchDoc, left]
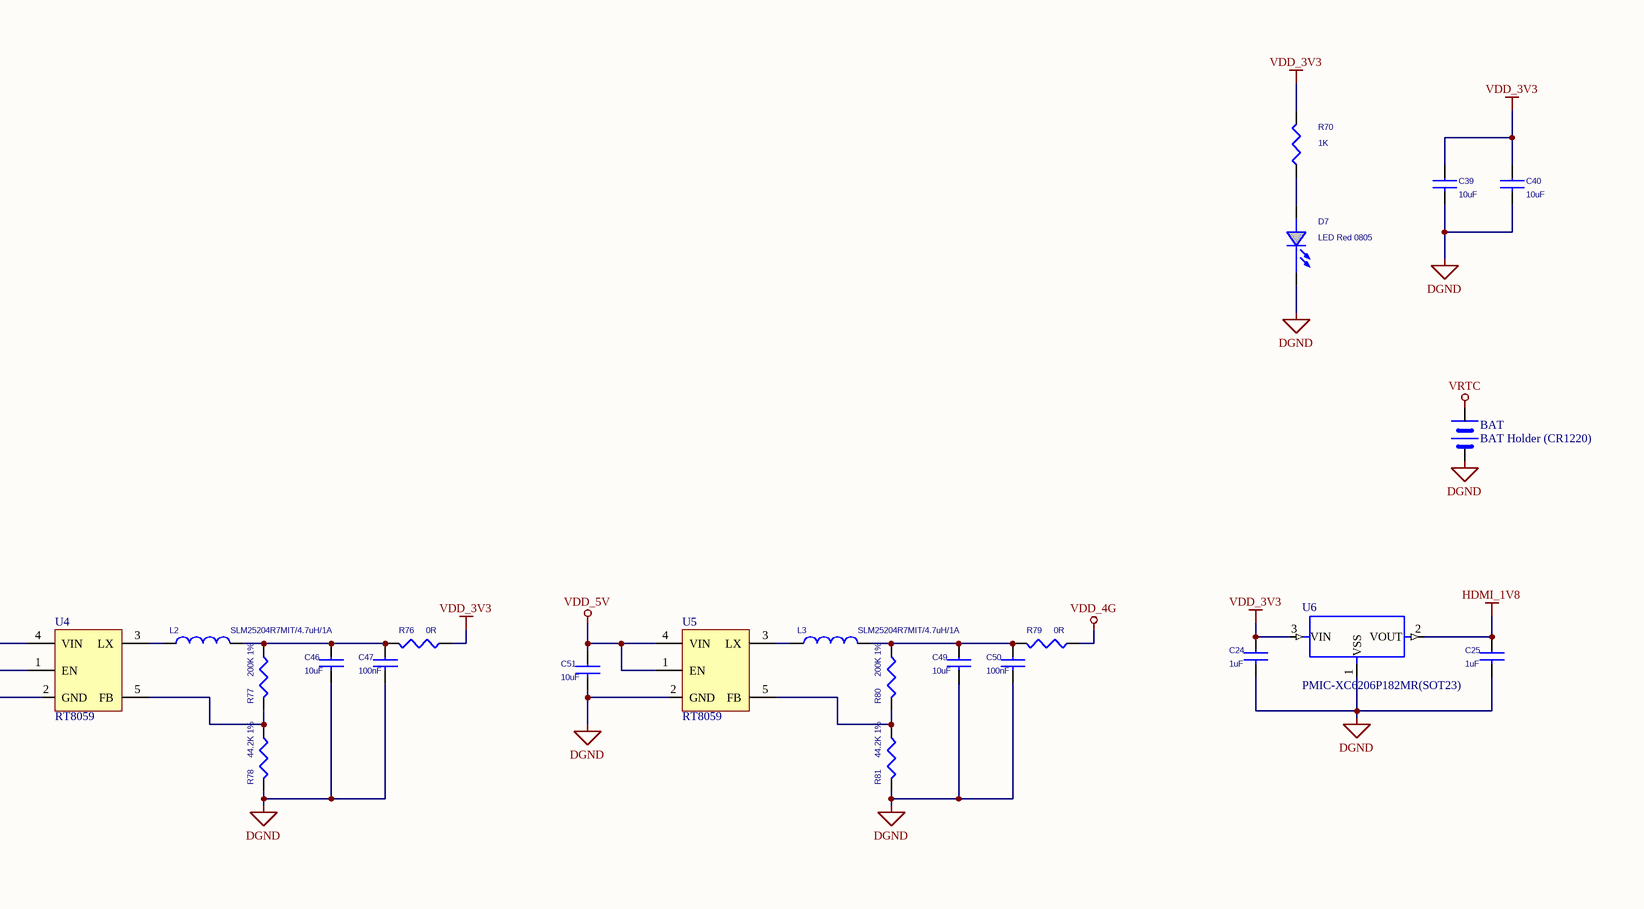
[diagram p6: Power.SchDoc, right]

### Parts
BAT  BAT Holder (CR1220)  [BAT600]
C24  1uF  [C0603]
C25  1uF  [C0603]
C36  100nF/50V  [C0603]
C37  22uF  [C1206]
C38  220uF/10V  [CAPSOP]
C39  10uF  [C0603]
C40  10uF  [C0603]
C41  100uF/50V  [capsop]
C42  10uF/50V  [C1206]
C43  4.7nF  [C0603]
C44  39pF  [C0603]
C45  10nF  [C0603]
C46  10uF  [C0603]
C47  100nF  [C0603]
C48  10uF  [C0603]
C49  10uF  [C0603]
C50  100nF  [C0603]
C51  10uF  [C0603]
D6  SSA33L/SS34  [DO-214AC-SMA-12]
D7  LED Red 0805  [LED]
D8  SMAJ12A  [do-214ac-sma-12]
L1  SWPA6045S6R8MT/6.8uH/3.5A  [L7x7]
L2  SLM25204R7MIT/4.7uH/1A  [L1210]
L3  SLM25204R7MIT/4.7uH/1A  [L1210]
PWR_HDR  XH 2.54 4Pin  [JST_XHP-4]
PWR_IN  DC Plug (5.5*2.1) DC-005  [DC-0005]
PWR_SW  Power Switch (SS12F44)  [SW35]  (value not drawn)
R6  NC (49.9K)  [R0603]
R70  1K  [R0603]
R71  62K/1%  [R0603]
R72  1K/1%  [R0603]
R73  NC (365K)  [R0603]
R74  12K/1%  [R0603]
R75  49.9K  [R0603]
R76  0R  [R0603]
R77  200K 1%  [R0603]
R78  44.2K 1%  [R0603]
R79  0R  [R0603]
R80  200K 1%  [R0603]
R81  44.2K 1%  [R0603]
U3  tps54332d  [SOIC8-50X204-TH-2]
U4  RT8059  [SOT95P280X100-5N]
U5  RT8059  [SOT95P280X100-5N]
U6  PMIC-XC6206P182MR(SOT23)  [SOT-23]

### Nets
DGND: BAT.2 C24.2 C25.2 C37.2 C38.2 C39.2 C40.2 C41.2 C42.2 C44.2 C45.2 C46.2 C47.2 C48.2 C49.2 C50.2 C51.2 D6.1(A) D7.2(CATHODE) D8.1(A) PWR_HDR.3 PWR_HDR.4 PWR_IN.2 PWR_IN.2A PWR_IN.2B PWR_IN.3 PWR_IN.3A PWR_IN.3B R6.2 R74.2 R75.2 R78.2(P2) R81.2(P2) U3.7(GND) U3.9(PWR_PAD) U4.2(GND) U5.2(GND) U6.1(VSS)
HDMI_1V8: C25.1 U6.2(VOUT)
VDD_3V3: C24.1 C39.1 C40.1 R70.2 R76.1(P1) U6.3(VIN)
VDD_4G: R79.1(P1)
VDD_5V: C37.1 C38.1 C48.1 C51.1 L1.2 R71.1 U4.1(EN) U4.4(VIN) U5.1(EN) U5.4(VIN)
VDD_12V: C41.1 C42.1 D8.2(K) PWR_SW.4 R73.1 U3.2(VIN)
VIN: PWR_HDR.1 PWR_HDR.2 PWR_IN.1 PWR_IN.1A PWR_IN.1B PWR_SW.2 PWR_SW.3
VRTC: BAT.1
NetC36_1: C36.1 U3.1(BOOT)
NetC36_2: C36.2 D6.2(K) L1.1 U3.8(PH)
NetC43_1: C43.1 C44.1 U3.6(COMP)
NetC43_2: C43.2 R75.1
NetC45_1: C45.1 R6.1 U3.4(SS)
NetC46_1: C46.1 C47.1 L2.2 R76.2(P2) R77.1(P1)
NetC49_1: C49.1 C50.1 L3.2 R79.2(P2) R80.1(P1)
NetD7_1: D7.1(ANODE) R70.1
NetL2_1: L2.1 U4.3(LX)
NetL3_1: L3.1 U5.3(LX)
NetR71_2: R71.2 R72.1
NetR72_2: R72.2 R74.1 U3.5(VSENS)
NetR73_2: R73.2 U3.3(EN)
NetR77_2: R77.2(P2) R78.1(P1) U4.5(FB)
NetR80_2: R80.2(P2) R81.1(P1) U5.5(FB)

Not connected (* = marked no-connect by the designer): PWR_SW 1* 5*

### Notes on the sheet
- 5V, 3.5A
- (near U3) VSENSE=0.8V

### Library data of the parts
BAT = BATTERY
C24 C25 C46-C51 = 4.7uFCapacitor16V10%0603: TIIntPartnumber: 1C0103; MfrNum: EMK107ABJ475KA-T; Mfr: Taiyo Yuden; PartName: 4.7uF16V10%SMD0603; Cost10K: 0.00590; Cost100: 0.0198; Vendor: Digikey; DescriptiveText: Capacitor Ceramic 4.7uF 16V 10% 0603
C36 C37 C39 C40 C42-C45 = CAP NP
C38 = CAP_0: SMD,6.3x5.4mm
C41 = CAP: SMD,6.3x7.7mm
D6 = DIODE_0
D7 = LED
D8 = DIODE ZENER1_8
L1 = INDUCTOR
L2 L3 = 2.2uHInductor10%2_0.6Asmd: PartName: 2.2uH10%2.6Asmd; Mfr: TDK; MfrNum: VLCF5020T-2R2N2R6-3; TIIntPartnumber: 1L0025; DescriptiveText: Inductor 2.2uH smt 2.6A, 58 milliohm; Vendor: Digikey; Cost100: 1.11; Cost10K: 0.3501
PWR_HDR = Header 4
PWR_IN = PWR2.5
PWR_SW = Header 5
R6 R70-R75 = R
R76-R81 = 10KOhmResistor1/16W0402_Dup1: TIIntPartnumber: 1R0168; MfrNum: MCR01MZPJ103; Mfr: Rohm; PartName: 10Kohm1/16W5%SMD0402; Descriptive_Text: Resistor 10Kohm 1/16W 5% 0402; Cost10K: 0.0017; Cost100: 0.03; Vendor: Digikey
U6 = PMIC-XC6206P182MR(SOT23): Linear Voltage Regulator IC Output; MF: Torex

## Sheet SDCard.SchDoc
size 279 x 127 mm; SheetNumber: 14
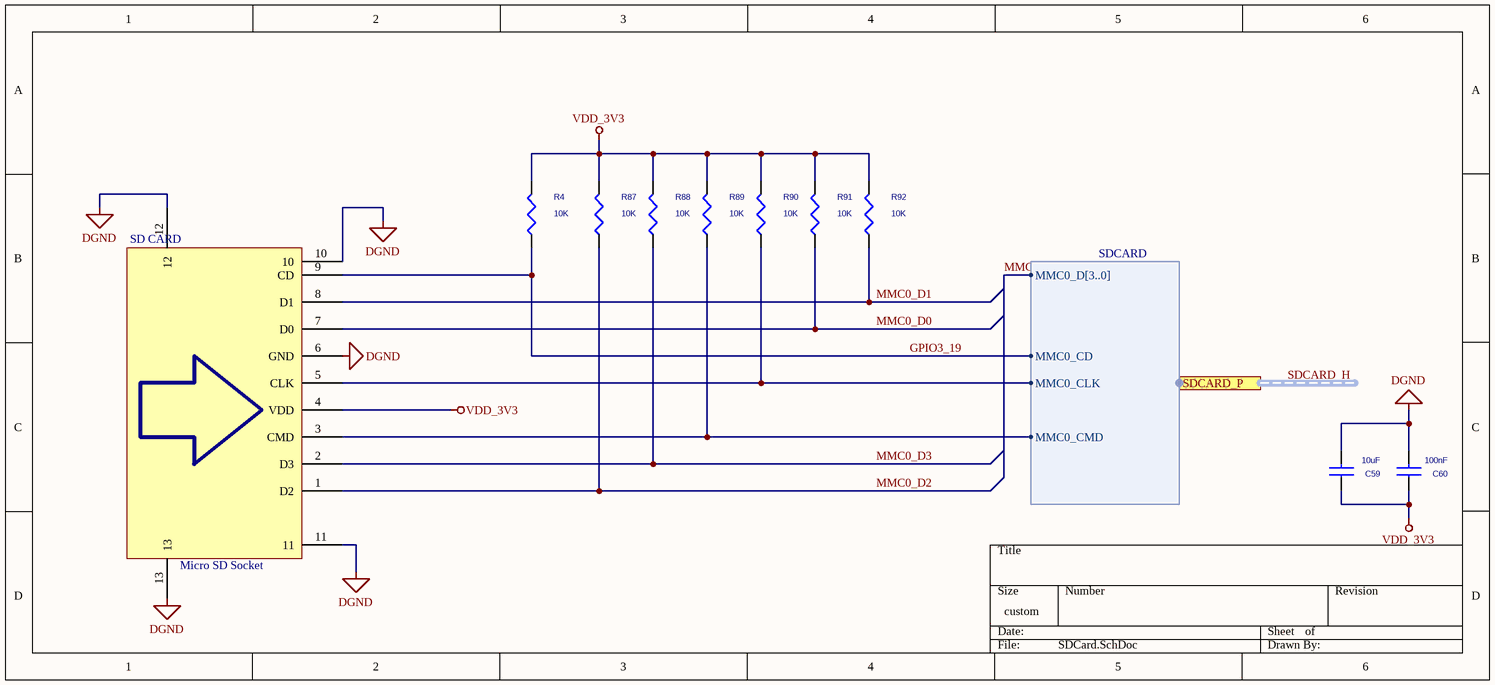
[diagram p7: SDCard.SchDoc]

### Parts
C59  10uF  [C0603]
C60  100nF  [C0603]
R4  10K  [R0603]
R87  10K  [R0603]
R88  10K  [R0603]
R89  10K  [R0603]
R90  10K  [R0603]
R91  10K  [R0603]
R92  10K  [R0603]
SD_CARD  Micro SD Socket  [uSD]

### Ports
SDCARD_P (harness SDCARD)

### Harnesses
SDCARD: MMC0_CLK, MMC0_CMD, MMC0_D[3..0], MMC0_CD

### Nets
DGND: C59.2 C60.2 SD_CARD.6(GND) SD_CARD.10 SD_CARD.11 SD_CARD.12 SD_CARD.13
VDD_3V3: C59.1 C60.1 R4.2 R87.2 R88.2 R89.2 R90.2 R91.2 R92.2 SD_CARD.4(VDD)
GPIO3_19: R4.1 SD_CARD.9(CD) ; port SDCARD_P.MMC0_CD
MMC0_CLK: R90.1 SD_CARD.5(CLK) ; port SDCARD_P.MMC0_CLK
MMC0_CMD: R89.1 SD_CARD.3(CMD) ; port SDCARD_P.MMC0_CMD
MMC0_D0: R91.1 SD_CARD.7(D0)
MMC0_D1: R92.1 SD_CARD.8(D1)
MMC0_D2: R87.1 SD_CARD.1(D2)
MMC0_D3: R88.1 SD_CARD.2(D3)

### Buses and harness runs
bus MMC0_D[3..0]
harness SDCARD_H = port SDCARD_P

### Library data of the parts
C59 C60 = CAP NP
R4 R87-R92 = R
SD_CARD = Component_1

## Sheet Sound.SchDoc
size 152 x 101 mm; SheetNumber: 7
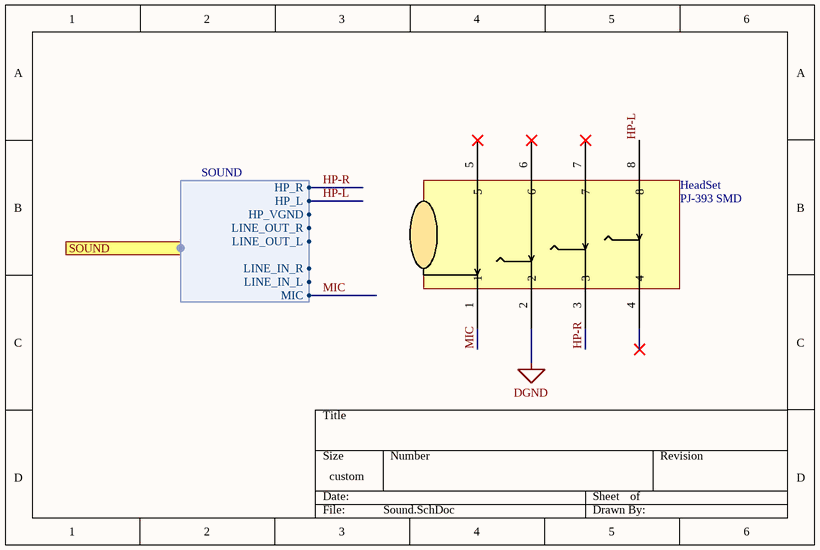
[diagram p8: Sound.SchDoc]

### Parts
HeadSet  PJ-393 SMD  [PJ-393]

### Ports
SOUND (harness SOUND)

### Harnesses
SOUND: HP_R, HP_L, HP_VGND, LINE_OUT_R, LINE_OUT_L, LINE_IN_R, LINE_IN_L, MIC

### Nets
DGND: HeadSet.2 ; port SOUND.HP_VGND
HP-L: HeadSet.8 ; port SOUND.HP_L
HP-R: HeadSet.3 ; port SOUND.HP_R
MIC: HeadSet.1 ; port SOUND.MIC

Not connected (* = marked no-connect by the designer): HeadSet 4* 5* 6* 7*

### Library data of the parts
HeadSet = PJ-393

## Sheet Config.SchDoc
size 228 x 101 mm
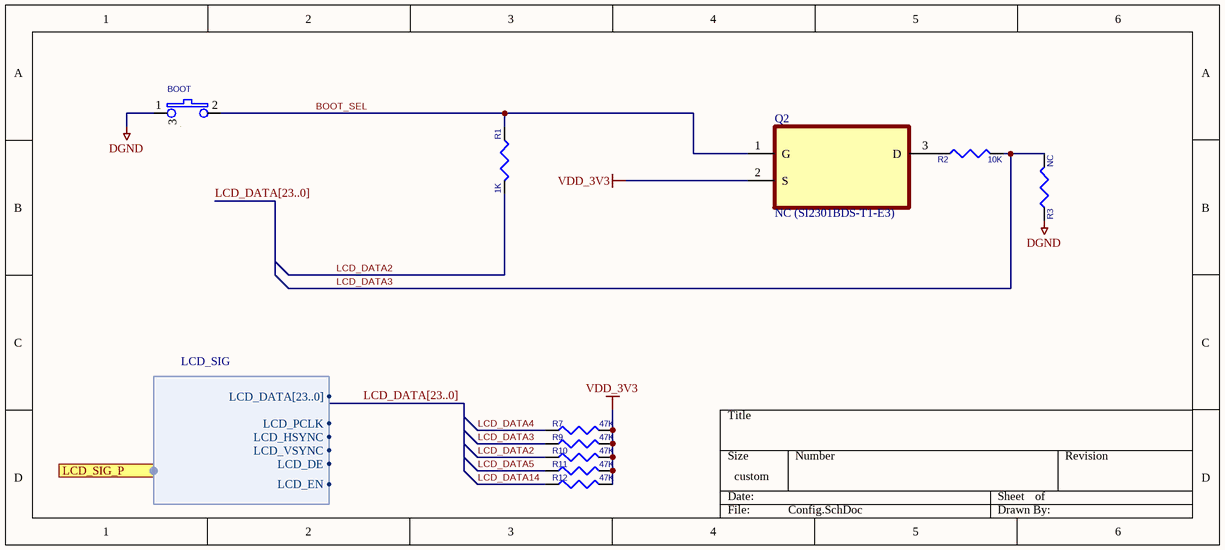
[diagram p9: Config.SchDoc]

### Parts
BOOT  Push Button Right  [KEY-A06]  (value not drawn)
Q2  NC (SI2301BDS-T1-E3)  [SOT-23]
R1  1K  [R0603]
R2  10K  [R0603]
R3  NC  [R0603]
R7  47K  [R0603]
R9  47K  [R0603]
R10  47K  [R0603]
R11  47K  [R0603]
R12  47K  [R0603]

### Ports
LCD_SIG_P (harness LCD_SIG)

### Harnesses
LCD_SIG: LCD_DATA[23..0], LCD_PCLK, LCD_HSYNC, LCD_VSYNC, LCD_DE, LCD_EN

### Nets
DGND: BOOT.1 R3.1
VDD_3V3: Q2.2(S) R7.1(P1) R9.1(P1) R10.1(P1) R11.1(P1) R12.1(P1)
BOOT_SEL: BOOT.2 Q2.1(G) R1.1
LCD_DATA2: R1.2 R10.2(P2)
LCD_DATA3: R2.2 R3.2 R9.2(P2)
LCD_DATA4: R7.2(P2)
LCD_DATA5: R11.2(P2)
LCD_DATA14: R12.2(P2)
NetQ2_3: Q2.3(D) R2.1

Not connected (* = marked no-connect by the designer): BOOT 3

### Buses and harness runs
bus LCD_DATA[23..0]

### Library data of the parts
BOOT = SW PUSHBUTTON_0
Q2 = SI2301BDS-T1-E3: P-Channel 20V 2.2A _Ta_ 700mW _Ta_ Surface Mount SOT-23-3 _TO-236_; MF: Vishay
R1-R3 = R
R7 R9-R12 = RES SMD: Manufacturer: Yageo; Manufacturer Part Number: RC0402FR-071K5L; Resistance (Ohms): 1.5k; Power (Watts): 0.063W, 1/16W; Temperature Coefficient: ±100ppm/°C; Tolerance: ±1%

## Sheet USBHUB2.SchDoc
size A3
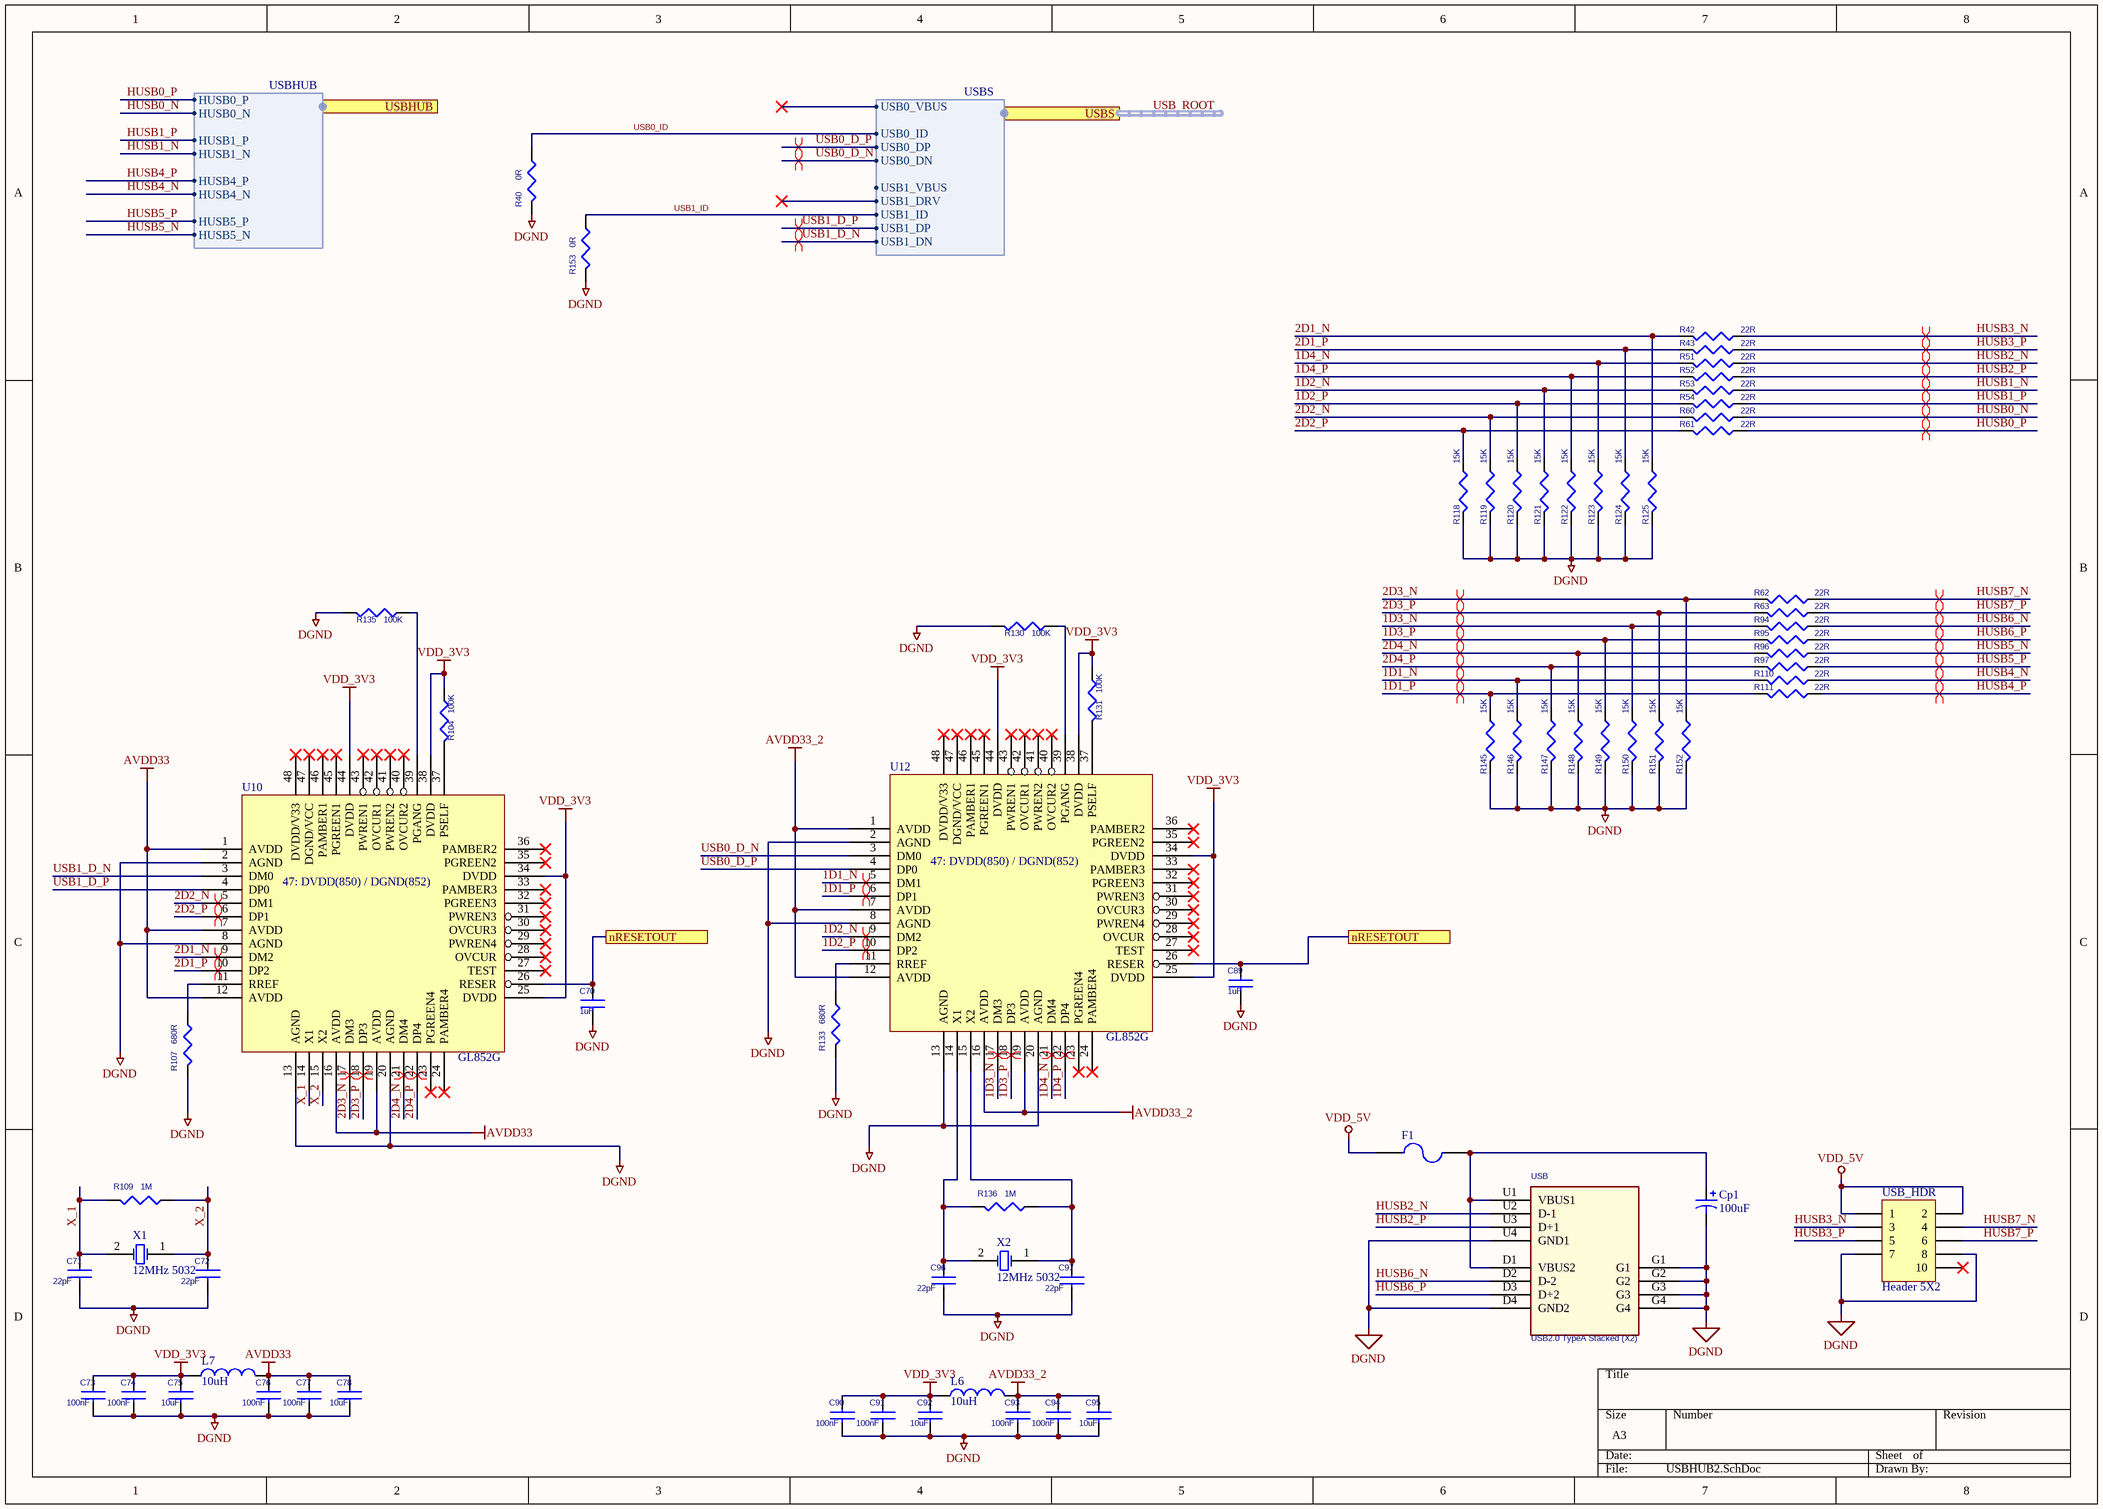
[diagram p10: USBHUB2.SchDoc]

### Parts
C70  1uF  [C0603]
C71  22pF  [C0603]
C72  22pF  [C0603]
C73  100nF  [C0603]
C74  100nF  [C0603]
C75  10uF  [C0603]
C76  100nF  [C0603]
C77  100nF  [C0603]
C78  10uF  [C0603]
C89  1uF  [C0603]
C90  100nF  [C0603]
C91  100nF  [C0603]
C92  10uF  [C0603]
C93  100nF  [C0603]
C94  100nF  [C0603]
C95  10uF  [C0603]
C96  22pF  [C0603]
C97  22pF  [C0603]
Cp1  100uF  [C1210]
F1  Fuse 1A  [F1206]  (value not drawn)
L6  10uH  [L0603]
L7  value 10uH  [L0603]  (hidden comment: 10uH 200mA)
R40  0R  [R0603]
R42  22R  [R0603]
R43  22R  [R0603]
R51  22R  [R0603]
R52  22R  [R0603]
R53  22R  [R0603]
R54  22R  [R0603]
R60  22R  [R0603]
R61  22R  [R0603]
R62  22R  [R0603]
R63  22R  [R0603]
R94  22R  [R0603]
R95  22R  [R0603]
R96  22R  [R0603]
R97  22R  [R0603]
R104  100K  [R0603]
R107  680R  [R0603]
R109  1M  [R0603]
R110  22R  [R0603]
R111  22R  [R0603]
R118  15K  [R0603]
R119  15K  [R0603]
R120  15K  [R0603]
R121  15K  [R0603]
R122  15K  [R0603]
R123  15K  [R0603]
R124  15K  [R0603]
R125  15K  [R0603]
R130  100K  [R0603]
R131  100K  [R0603]
R133  680R  [R0603]
R135  100K  [R0603]
R136  1M  [R0603]
R145  15K  [R0603]
R146  15K  [R0603]
R147  15K  [R0603]
R148  15K  [R0603]
R149  15K  [R0603]
R150  15K  [R0603]
R151  15K  [R0603]
R152  15K  [R0603]
R153  0R  [R0603]
U10  GL852G  [TSQFP50P900X900X160-48N]
U12  GL852G  [TSQFP50P900X900X160-48N]
USB  USB2.0 TypeA Stacked (X2)  [USB_DUAL_C080073-2]
USB_HDR  Header 5X2  [HDR2X5]
X1  12MHz 5032  [CRYSTAL-5032-2p]
X2  12MHz 5032  [CRYSTAL-5032-2p]

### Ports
nRESETOUT, USBHUB (harness USBHUB), USBS (harness USBS)

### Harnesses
USBS: USB0_ID, USB0_VBUS, USB0_DP, USB0_DN, USB1_ID, USB1_VBUS, USB1_DP, USB1_DN, USB1_DRV
USBHUB: HUSB0_P, HUSB0_N, HUSB1_P, HUSB1_N, HUSB4_P, HUSB4_N, HUSB5_P, HUSB5_N

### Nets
AVDD33: C76.1 C77.1 C78.1 L7.2 U10.1(AVDD) U10.7(AVDD) U10.12(AVDD) U10.16(AVDD) U10.19(AVDD)
AVDD33_2: C93.1 C94.1 C95.1 L6.2 U12.1(AVDD) U12.7(AVDD) U12.12(AVDD) U12.16(AVDD) U12.19(AVDD)
DGND: C70.2 C71.2 C72.2 C73.2 C74.2 C75.2 C76.2 C77.2 C78.2 C89.2 C90.2 C91.2 C92.2 C93.2 C94.2 C95.2 C96.2 C97.2 Cp1.2 R40.2(P2) R107.2(P2) R118.2(P2) R119.2(P2) R120.2(P2) R121.2(P2) R122.2(P2) R123.2(P2) R124.2(P2) R125.2(P2) R130.2(P2) R133.2(P2) R135.2(P2) R145.2(P2) R146.2(P2) R147.2(P2) R148.2(P2) R149.2(P2) R150.2(P2) R151.2(P2) R152.2(P2) R153.2(P2) U10.2(AGND) U10.8(AGND) U10.13(AGND) U10.20(AGND) U12.2(AGND) U12.8(AGND) U12.13(AGND) U12.20(AGND) USB.D4(GND2) USB.G1 USB.G2 USB.G3 USB.G4 USB.U4(GND1) USB_HDR.7 USB_HDR.8
VDD_3V3: C73.1 C74.1 C75.1 C90.1 C91.1 C92.1 L6.1 L7.1 R104.1(P1) R131.1(P1) U10.25(DVDD) U10.34(DVDD) U10.38(DVDD) U10.44(DVDD) U12.25(DVDD) U12.34(DVDD) U12.38(DVDD) U12.44(DVDD)
VDD_5V: F1.2 USB_HDR.1 USB_HDR.2
1D1_N: R110.2(P2) R146.1(P1) U12.5(DM1)
1D1_P: R111.2(P2) R145.1(P1) U12.6(DP1)
1D2_N: R53.2(P2) R121.1(P1) U12.9(DM2)
1D2_P: R54.2(P2) R120.1(P1) U12.10(DP2)
1D3_N: R94.2(P2) R150.1(P1) U12.17(DM3)
1D3_P: R95.2(P2) R149.1(P1) U12.18(DP3)
1D4_N: R51.2(P2) R123.1(P1) U12.21(DM4)
1D4_P: R52.2(P2) R122.1(P1) U12.22(DP4)
2D1_N: R42.2(P2) R125.1(P1) U10.9(DM2)
2D1_P: R43.2(P2) R124.1(P1) U10.10(DP2)
2D2_N: R60.2(P2) R119.1(P1) U10.5(DM1)
2D2_P: R61.2(P2) R118.1(P1) U10.6(DP1)
2D3_N: R62.2(P2) R152.1(P1) U10.17(DM3)
2D3_P: R63.2(P2) R151.1(P1) U10.18(DP3)
2D4_N: R96.2(P2) R148.1(P1) U10.21(DM4)
2D4_P: R97.2(P2) R147.1(P1) U10.22(DP4)
HUSB0_N: R60.1(P1) ; port USBHUB.HUSB0_N
HUSB0_P: R61.1(P1) ; port USBHUB.HUSB0_P
HUSB1_N: R53.1(P1) ; port USBHUB.HUSB1_N
HUSB1_P: R54.1(P1) ; port USBHUB.HUSB1_P
HUSB2_N: R51.1(P1) USB.U2(D-1)
HUSB2_P: R52.1(P1) USB.U3(D+1)
HUSB3_N: R42.1(P1) USB_HDR.3
HUSB3_P: R43.1(P1) USB_HDR.5
HUSB4_N: R110.1(P1) ; port USBHUB.HUSB4_N
HUSB4_P: R111.1(P1) ; port USBHUB.HUSB4_P
HUSB5_N: R96.1(P1) ; port USBHUB.HUSB5_N
HUSB5_P: R97.1(P1) ; port USBHUB.HUSB5_P
HUSB6_N: R94.1(P1) USB.D2(D-2)
HUSB6_P: R95.1(P1) USB.D3(D+2)
HUSB7_N: R62.1(P1) USB_HDR.4
HUSB7_P: R63.1(P1) USB_HDR.6
RESETOUTn: C70.1 C89.1 U10.26(RESER) U12.26(RESER) ; port nRESETOUT
USB0_D_N: U12.3(DM0) ; port USBS.USB0_DN
USB0_D_P: U12.4(DP0) ; port USBS.USB0_DP
USB0_ID: R40.1(P1) ; port USBS.USB0_ID
USB1_D_N: U10.3(DM0) ; port USBS.USB1_DN
USB1_D_P: U10.4(DP0) ; port USBS.USB1_DP
USB1_ID: R153.1(P1) ; port USBS.USB1_ID
X_1: C71.1 R109.2(P2) U10.14(X1) X1.2(OSC2)
X_2: C72.1 R109.1(P1) U10.15(X2) X1.1(OSC1)
NetC96_1: C96.1 R136.2(P2) U12.14(X1) X2.2(OSC2)
NetC97_1: C97.1 R136.1(P1) U12.15(X2) X2.1(OSC1)
NetCp1_1: Cp1.1 F1.1 USB.D1(VBUS2) USB.U1(VBUS1)
NetR104_2: R104.2(P2) U10.37(PSELF)
NetR107_1: R107.1(P1) U10.11(RREF)
NetR130_1: R130.1(P1) U12.39(PGANG)
NetR131_2: R131.2(P2) U12.37(PSELF)
NetR133_1: R133.1(P1) U12.11(RREF)
NetR135_1: R135.1(P1) U10.39(PGANG)

Not connected (* = marked no-connect by the designer): U10 23(PGREEN4)* 24(PAMBER4)* 27(TEST)* 28(OVCUR)* 29(PWREN4)* 30(OVCUR3)* 31(PWREN3)* 32(PGREEN3)* 33(PAMBER3)* 35(PGREEN2)* 36(PAMBER2)* 40(OVCUR2)* 41(PWREN2)* 42(OVCUR1)* 43(PWREN1)* 45(PGREEN1)* 46(PAMBER1)* 47(DGND/VCC)* 48(DVDD/V33)*; U12 23(PGREEN4)* 24(PAMBER4)* 27(TEST)* 28(OVCUR)* 29(PWREN4)* 30(OVCUR3)* 31(PWREN3)* 32(PGREEN3)* 33(PAMBER3)* 35(PGREEN2)* 36(PAMBER2)* 40(OVCUR2)* 41(PWREN2)* 42(OVCUR1)* 43(PWREN1)* 45(PGREEN1)* 46(PAMBER1)* 47(DGND/VCC)* 48(DVDD/V33)*; USB_HDR 10*

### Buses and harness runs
harness USB_ROOT = port USBS

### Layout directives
differential pair: 1D1_N, 1D1_P, 1D2_N, 1D2_P, 1D3_N, 1D3_P, 1D4_N, 1D4_P, 2D1_N, 2D1_P, 2D2_N, 2D2_P, 2D3_N, 2D3_P, 2D4_N, 2D4_P, HUSB0_N, HUSB0_P, HUSB1_N, HUSB1_P, HUSB2_N, HUSB2_P, HUSB3_N, HUSB3_P, HUSB4_N, HUSB4_P, HUSB5_N, HUSB5_P, HUSB6_N, HUSB6_P, HUSB7_N, HUSB7_P, USB0_D_N, USB0_D_P, USB1_D_N, USB1_D_P

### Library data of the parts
C70-C78 C89-C97 = CAP NP
Cp1 = Cap Pol3: Polarized Capacitor (Surface Mount); Value: 100pF
F1 = Fuse 2: Fuse 1A (1206)
L6 = Inductor: 12 x 12 3A power inductor SMD; Code_IEC: 1005
L7 = Inductor: Code_IEC: 1005
R40 R42 R43 R51-R54 R60-R63 R94-R97 R104 R107 R109-R111 R118-R125 R130 R131 R133 R135 R136 R145-R153 = 10KOhmResistor1/16W0402_Dup1: as R76 on sheet Power
U10 U12 = GL850/2
USB = USB-HOST_0
USB_HDR = Header 5X2: Header, 5-Pin, Dual row
X1 X2 = XTAL

## Sheet UARTS.SchDoc
size 254 x 241 mm
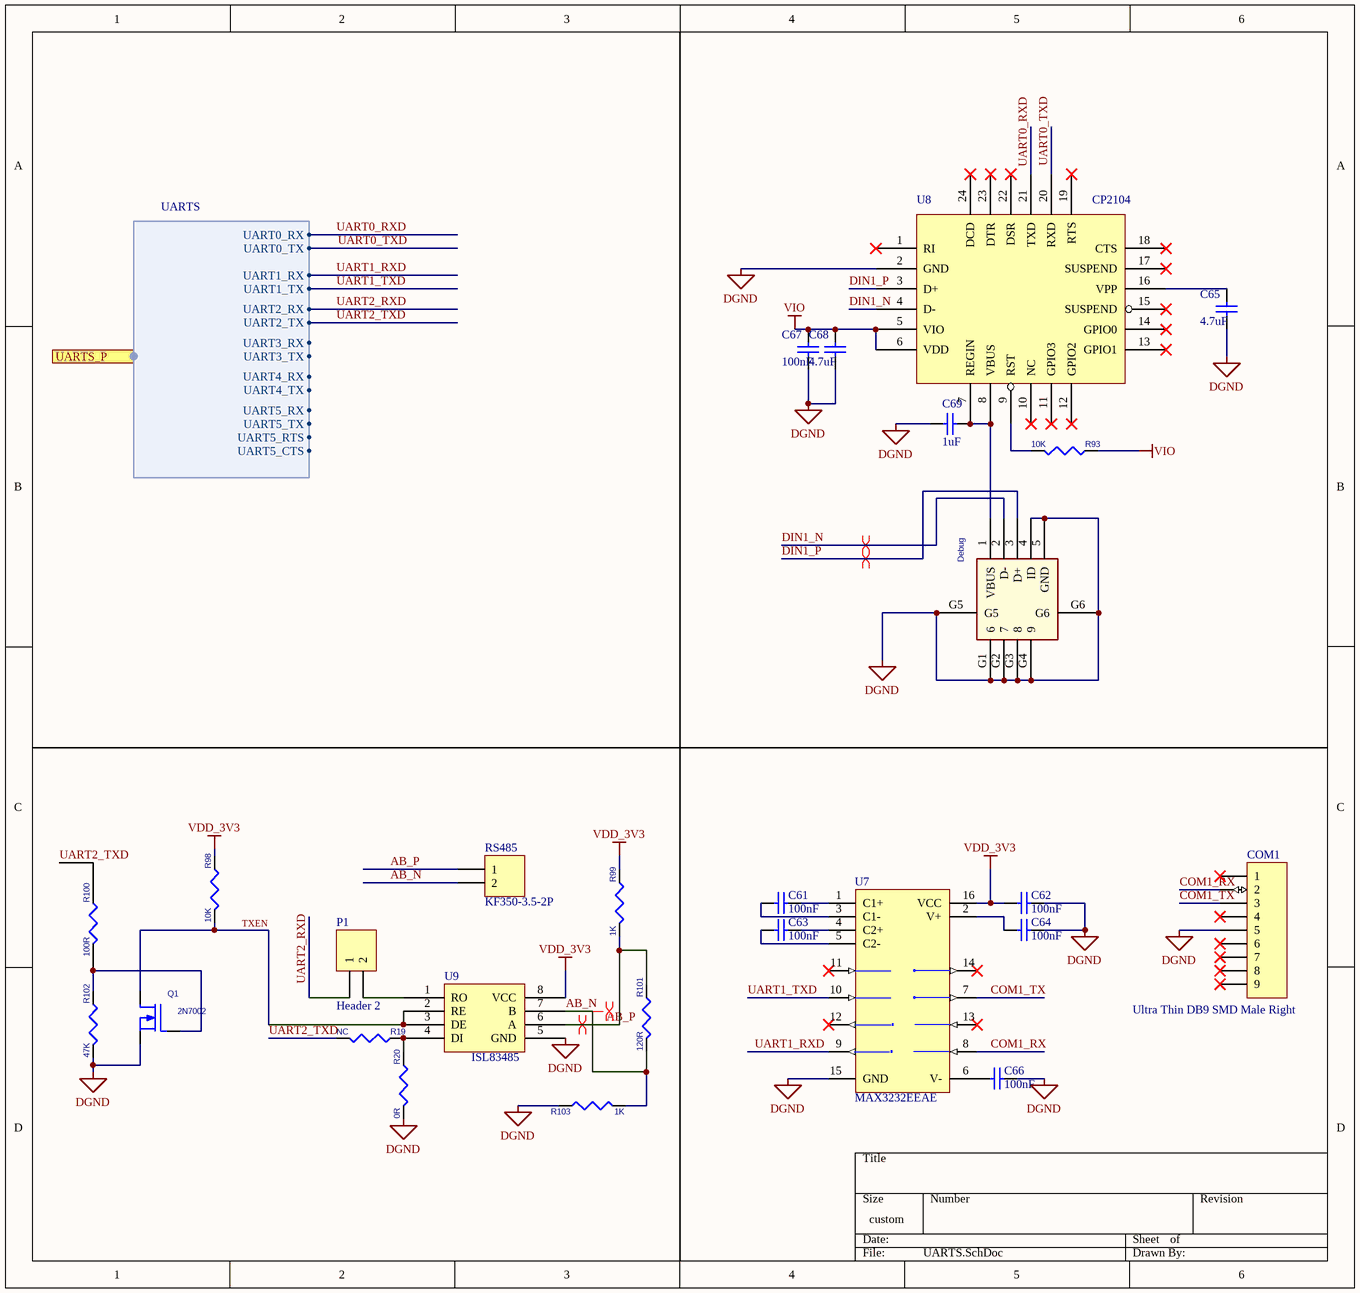
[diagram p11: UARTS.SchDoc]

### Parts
C61  100nF  [C0603]
C62  100nF  [C0603]
C63  100nF  [C0603]
C64  100nF  [C0603]
C65  4.7uF  [C0603]
C66  100nF  [C0603]
C67  100nF  [C0603]
C68  4.7uF  [C0603]
C69  1uF  [C0603]
COM1  Ultra Thin DB9 SMD Male Right  [DB9-UltraThin]
Debug  MicroUSB  [micro_USB-B_hrs_ZX62D-B-5PA8]  (value not drawn)
P1  Header 2  [HDR1X2]
Q1  2N7002  [S9013SMD]
R19  NC  [R0603]
R20  0R  [R0603]
R93  10K  [R0603]
R98  10K  [R0603]
R99  1K  [R0603]
R100  100R  [R0603]
R101  120R  [R0603]
R102  47K  [R0603]
R103  1K  [R0603]
RS485  KF350-3.5-2P  [Terminal_X2]
U7  MAX3232EEAE  [SSOP16]
U8  CP2104  [QFN50P400X400X75-24N]
U9  ISL83485  [max14840]

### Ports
UARTS_P (harness UARTS)

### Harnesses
UARTS: UART0_RX, UART0_TX, UART1_RX, UART1_TX, UART2_RX, UART2_TX, UART3_RX, UART3_TX, UART4_RX, UART4_TX, UART5_RX, UART5_TX, UART5_RTS, UART5_CTS

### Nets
DGND: C62.1 C64.1 C65.1 C66.1 C67.1 C68.1 C69.2 COM1.5 Debug.4(ID) Debug.5(GND) Debug.G1(6) Debug.G2(7) Debug.G3(8) Debug.G4(9) Debug.G5 Debug.G6 Q1.2(S) R20.2 R102.2 R103.1 U7.15(GND) U8.2(GND) U9.5(GND)
VDD_3V3: C62.2 R98.1 R99.1 U7.16(VCC) U9.8(VCC)
VIO: C67.2 C68.2 R93.1 U8.5(VIO) U8.6(VDD)
AB_N: R101.2 R103.2 RS485.2 U9.7(B)
AB_P: R99.2 R101.1 RS485.1 U9.6(A)
COM1_RX: COM1.2 U7.8(R2IN)
COM1_TX: COM1.3 U7.7(T2OUT)
DIN1_N: Debug.2(D-) U8.4(D-)
DIN1_P: Debug.3(D+) U8.3(D+)
TXEN: Q1.3(D) R98.2 U9.2(RE) U9.3(DE)
UART0_RXD: U8.21(TXD) ; port UARTS_P.UART0_RX
UART0_TXD: U8.20(RXD) ; port UARTS_P.UART0_TX
UART1_RXD: U7.9(R2OUT) ; port UARTS_P.UART1_RX
UART1_TXD: U7.10(T2IN) ; port UARTS_P.UART1_TX
UART2_RXD: P1.1 ; port UARTS_P.UART2_RX
UART2_TXD: R19.2 R100.1 ; port UARTS_P.UART2_TX
NetC61_1: C61.1 U7.1(C1+)
NetC61_2: C61.2 U7.3(C1-)
NetC63_1: C63.1 U7.5(C2-)
NetC63_2: C63.2 U7.4(C2+)
NetC64_2: C64.2 U7.2(V+)
NetC65_2: C65.2 U8.16(VPP)
NetC66_2: C66.2 U7.6(V-)
NetC69_1: C69.1 Debug.1(VBUS) U8.7(REGIN) U8.8(VBUS)
NetP1_2: P1.2 U9.1(RO)
NetQ1_1: Q1.1(G) R100.2 R102.1
NetR19_1: R19.1 R20.1 U9.4(DI)
NetR93_2: R93.2 U8.9(RST)

Not connected (* = marked no-connect by the designer): COM1 1* 4* 6* 7* 8* 9*; U7 11(T1IN)* 12(R1OUT)* 13(R1IN)* 14(T1OUT)*; U8 1(RI)* 10(NC)* 11(GPIO3)* 12(GPIO2)* 13(GPIO1)* 14(GPIO0)* 15(SUSPEND)* 17(SUSPEND)* 18(CTS)* 19(RTS)* 22(DSR)* 23(DTR)* 24(DCD)*

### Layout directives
differential pair: AB_N, AB_P, DIN1_N, DIN1_P

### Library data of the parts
C61-C69 = Cap Semi: Capacitor (Semiconductor SIM Model)
COM1 = Header 9
Debug = miniusb_0
P1 = Header 2: Header, 2-Pin
Q1 = MOSFET_N_DMG1012T_Dup1: MOSFET, N, LOW VT, LOGIC; pin to pad: 1>B 2>E 3>C; Manufacturer: Diodes Inc
R19 R20 R93 R98-R103 = R
RS485 = Header 2
U7 = MAX3232EEAE: ±15kV ESD-Protected, 3.0V to 5.5V, Low-Power, up to 250kbps, True RS-232 Transceiver
U9 = Component_1: +3.3V Powered, HALF DUBLEX RS-485 Driver/Receiver,8 SO PACKAGE

## Sheet Others.SchDoc
size 177 x 279 mm
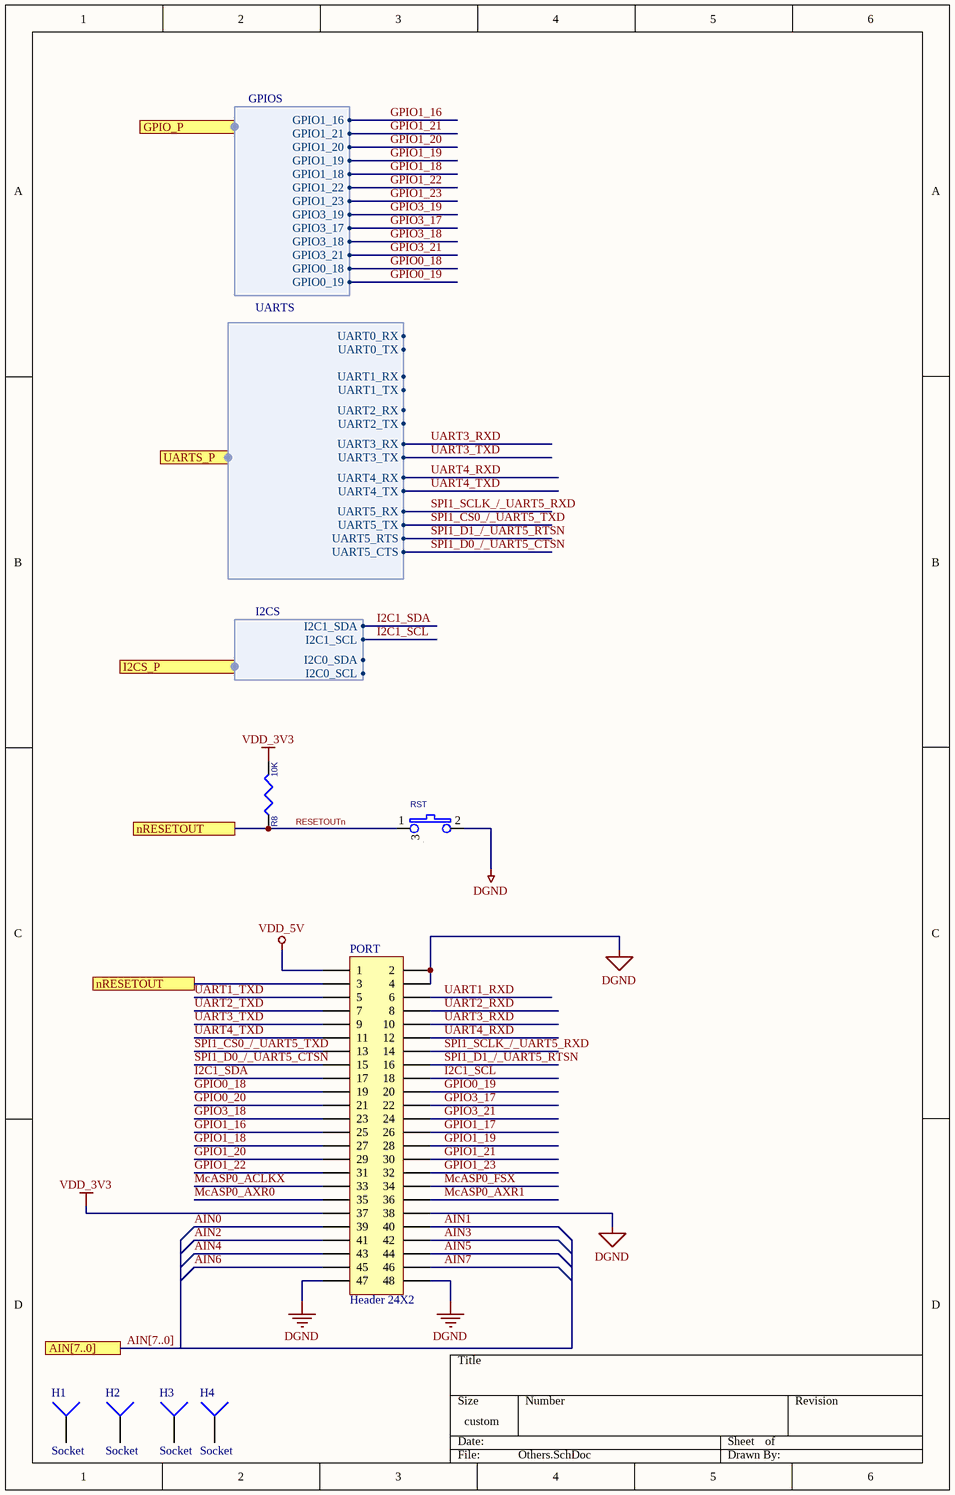
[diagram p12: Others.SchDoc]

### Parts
H1  Socket  [HOLE320-4H]  (no BOM)
H2  Socket  [HOLE320-4H]  (no BOM)
H3  Socket  [HOLE320-4H]  (no BOM)
H4  Socket  [HOLE320-4H]  (no BOM)
PORT  Header 24X2  [HDR2X24]
R8  10K  [R0603]
RST  Push Button Right  [KEY-A06]  (value not drawn)

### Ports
AIN[7..0], GPIO_P (harness GPIOS), I2CS_P (harness I2CS), nRESETOUT, UARTS_P (harness UARTS)

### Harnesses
UARTS: UART0_RX, UART0_TX, UART1_RX, UART1_TX, UART2_RX, UART2_TX, UART3_RX, UART3_TX, UART4_RX, UART4_TX, UART5_RX, UART5_TX, UART5_RTS, UART5_CTS
I2CS: I2C0_SDA, I2C0_SCL, I2C1_SDA, I2C1_SCL
GPIOS: GPIO1_16, GPIO1_21, GPIO1_20, GPIO1_19, GPIO1_18, GPIO1_22, GPIO1_23, GPIO3_19, GPIO3_17, GPIO3_18, GPIO3_21, GPIO0_18, GPIO0_19

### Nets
DGND: PORT.2 PORT.4 PORT.38 PORT.47 PORT.48 RST.2
VDD_3V3: PORT.37 R8.2
VDD_5V: PORT.1
AIN0: PORT.39
AIN1: PORT.40
AIN2: PORT.41
AIN3: PORT.42
AIN4: PORT.43
AIN5: PORT.44
AIN6: PORT.45
AIN7: PORT.46
GPIO0_18: PORT.19 ; port GPIO_P.GPIO0_18
GPIO0_19: PORT.20 ; port GPIO_P.GPIO0_19
GPIO0_20: PORT.21
GPIO1_16: PORT.25 ; port GPIO_P.GPIO1_16
GPIO1_17: PORT.26
GPIO1_18: PORT.27 ; port GPIO_P.GPIO1_18
GPIO1_19: PORT.28 ; port GPIO_P.GPIO1_19
GPIO1_20: PORT.29 ; port GPIO_P.GPIO1_20
GPIO1_21: PORT.30 ; port GPIO_P.GPIO1_21
GPIO1_22: PORT.31 ; port GPIO_P.GPIO1_22
GPIO1_23: PORT.32 ; port GPIO_P.GPIO1_23
GPIO3_17: PORT.22 ; port GPIO_P.GPIO3_17
GPIO3_18: PORT.23 ; port GPIO_P.GPIO3_18
GPIO3_21: PORT.24 ; port GPIO_P.GPIO3_21
I2C0_SCL: port I2CS_P.I2C0_SDA, port I2CS_P.I2C0_SCL
I2C1_SCL: PORT.18 ; port I2CS_P.I2C1_SCL
I2C1_SDA: PORT.17 ; port I2CS_P.I2C1_SDA
McASP0_ACLKX: PORT.33
McASP0_AXR0: PORT.35
McASP0_AXR1: PORT.36
McASP0_FSX: PORT.34
RESETOUTn: PORT.3 R8.1 RST.1 ; port nRESETOUT
SPI1_CS0_/_UART5_TXD: PORT.13 ; port UARTS_P.UART5_TX
SPI1_D0_/_UART5_CTSN: PORT.15 ; port UARTS_P.UART5_CTS
SPI1_D1_/_UART5_RTSN: PORT.16 ; port UARTS_P.UART5_RTS
SPI1_SCLK_/_UART5_RXD: PORT.14 ; port UARTS_P.UART5_RX
UART1_RXD: PORT.6 ; port UARTS_P.UART1_RX
UART1_TXD: PORT.5 ; port UARTS_P.UART1_TX
UART2_RXD: PORT.8 ; port UARTS_P.UART2_RX
UART2_TXD: PORT.7 ; port UARTS_P.UART2_TX
UART3_RXD: PORT.10 ; port UARTS_P.UART3_RX
UART3_TXD: PORT.9 ; port UARTS_P.UART3_TX
UART4_RXD: PORT.12 ; port UARTS_P.UART4_RX
UART4_TXD: PORT.11 ; port UARTS_P.UART4_TX

Not connected (* = marked no-connect by the designer): H1 1; H2 1; H3 1; H4 1; RST 3

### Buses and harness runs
bus AIN[7..0] = port AIN[7..0]

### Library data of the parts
PORT = Header 24X2: Header, 24-Pin, Dual row
R8 = R
RST = SW PUSHBUTTON_0

## Sheet eMod-Wifi.SchDoc
size 304 x 152 mm
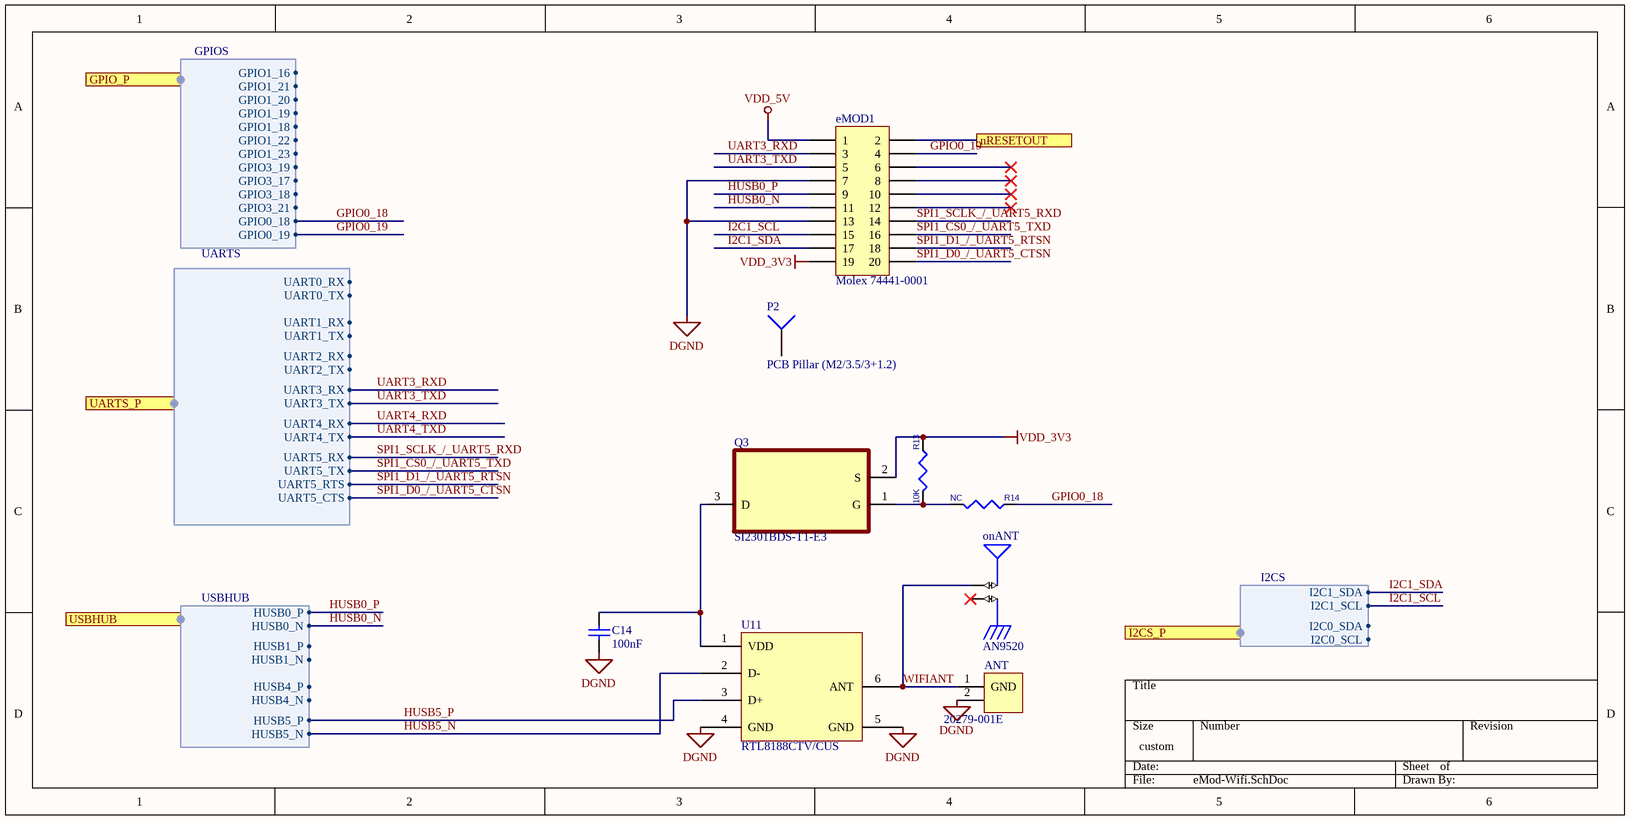
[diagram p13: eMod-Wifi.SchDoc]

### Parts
ANT  20279-001E  [IPXANT]
C14  100nF  [C0603]
eMOD1  Molex 74441-0001  [744410001]
onANT  AN9520  [SMD_ANT9520]
P2  PCB Pillar (M2/3.5/3+1.2)  [PCB Pillar]
Q3  SI2301BDS-T1-E3  [SOT-23]
R13  10K  [R0603]
R14  NC  [R0603]
U11  RTL8188CTV/CUS  [SOP200P1220X240-8N]

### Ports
GPIO_P (harness GPIOS), I2CS_P (harness I2CS), nRESETOUT, UARTS_P (harness UARTS), USBHUB (harness USBHUB)

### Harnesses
UARTS: UART0_RX, UART0_TX, UART1_RX, UART1_TX, UART2_RX, UART2_TX, UART3_RX, UART3_TX, UART4_RX, UART4_TX, UART5_RX, UART5_TX, UART5_RTS, UART5_CTS
I2CS: I2C0_SDA, I2C0_SCL, I2C1_SDA, I2C1_SCL
GPIOS: GPIO1_16, GPIO1_21, GPIO1_20, GPIO1_19, GPIO1_18, GPIO1_22, GPIO1_23, GPIO3_19, GPIO3_17, GPIO3_18, GPIO3_21, GPIO0_18, GPIO0_19
USBHUB: HUSB0_P, HUSB0_N, HUSB1_P, HUSB1_N, HUSB4_P, HUSB4_N, HUSB5_P, HUSB5_N

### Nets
DGND: ANT.2 C14.2 eMOD1.7 eMOD1.13 U11.4(GND) U11.5(GND)
VDD_3V3: eMOD1.19 Q3.2(S) R13.1
VDD_5V: eMOD1.1
GPIO0_18: R14.1 ; port GPIO_P.GPIO0_18
GPIO0_19: eMOD1.4 ; port GPIO_P.GPIO0_19
HUSB0_N: eMOD1.11 ; port USBHUB.HUSB0_N
HUSB0_P: eMOD1.9 ; port USBHUB.HUSB0_P
HUSB5_N: U11.2(D-) ; port USBHUB.HUSB5_N
HUSB5_P: U11.3(D+) ; port USBHUB.HUSB5_P
I2C0_SCL: port I2CS_P.I2C0_SDA, port I2CS_P.I2C0_SCL
I2C1_SCL: eMOD1.15 ; port I2CS_P.I2C1_SCL
I2C1_SDA: eMOD1.17 ; port I2CS_P.I2C1_SDA
RESETOUTn: eMOD1.2 ; port nRESETOUT
SPI1_CS0_/_UART5_TXD: eMOD1.16 ; port UARTS_P.UART5_TX
SPI1_D0_/_UART5_CTSN: eMOD1.20 ; port UARTS_P.UART5_CTS
SPI1_D1_/_UART5_RTSN: eMOD1.18 ; port UARTS_P.UART5_RTS
SPI1_SCLK_/_UART5_RXD: eMOD1.14 ; port UARTS_P.UART5_RX
UART3_RXD: eMOD1.3 ; port UARTS_P.UART3_RX
UART3_TXD: eMOD1.5 ; port UARTS_P.UART3_TX
WIFIANT: ANT.1(GND) onANT.P$FEED(FEED) U11.6(ANT)
NetC14_1: C14.1 Q3.3(D) U11.1(VDD)
NetQ3_1: Q3.1(G) R13.2 R14.2

Not connected (* = marked no-connect by the designer): eMOD1 6* 8* 10* 12*; onANT P$GND(GND)*; P2 1

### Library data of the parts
ANT = SMA
C14 = Cap Semi: Capacitor (Semiconductor SIM Model)
eMOD1 = Header 10X2
onANT = AN9520: SMD Built-in Antenna 2.4GHz;2P-L9.5*W2.1*H1.0mm RainSun;AN9520 SKU: 318010004
P2 = Socket
Q3 = SI2301BDS-T1-E3: as Q2 on sheet Config
R13 R14 = R
U11 = wifi_DJH_WF_68

## Sheet CAN.SchDoc
size 304 x 101 mm
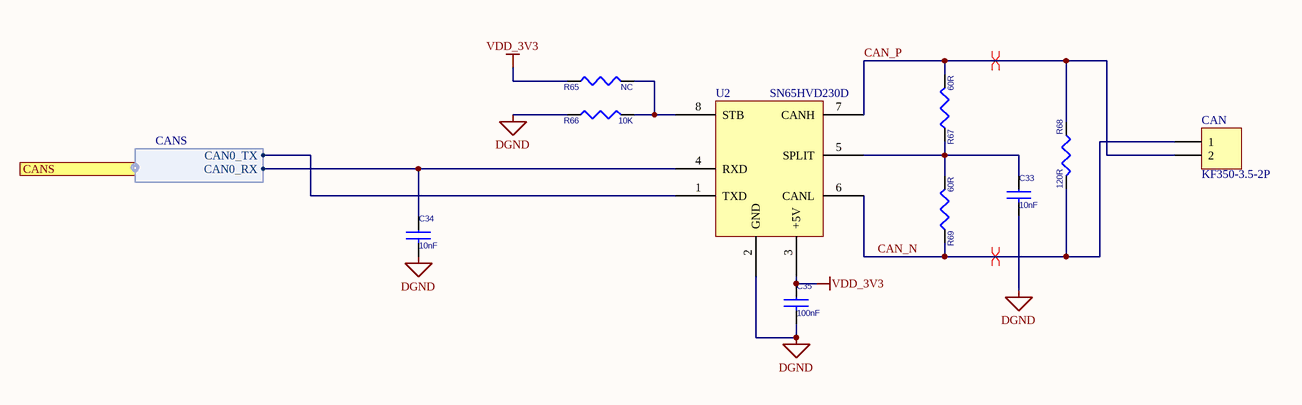
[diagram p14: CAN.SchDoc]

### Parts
C33  10nF  [C0603]
C34  10nF  [C0603]
C35  100nF  [C0603]
CAN  KF350-3.5-2P  [Terminal_X2]
R65  NC  [R0603]
R66  10K  [R0603]
R67  60R  [R0603]
R68  120R  [R0603]
R69  60R  [R0603]
U2  SN65HVD230D  [max14840]

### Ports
CANS (harness CANS)

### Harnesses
CANS: CAN0_TX, CAN0_RX

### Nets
DGND: C33.2 C34.2 C35.2 R66.1 U2.2(GND)
VDD_3V3: C35.1 R65.1 U2.3(+5V)
CAN0_RX: C34.1 U2.4(RXD) ; port CANS.CAN0_RX
CAN0_TX: U2.1(TXD) ; port CANS.CAN0_TX
CAN_N: CAN.1 R68.2 R69.1 U2.6(CANL)
CAN_P: CAN.2 R67.2 R68.1 U2.7(CANH)
NetC33_1: C33.1 R67.1 R69.2 U2.5(SPLIT)
NetR65_2: R65.2 R66.2 U2.8(STB)

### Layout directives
differential pair: CAN_N, CAN_P

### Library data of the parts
C33-C35 = CAP NP
CAN = Header 2
R65-R69 = R
U2 = Component_1: CAN Driver

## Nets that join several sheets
DGND: Display (36 pins), SODIMM-2 (30 pins), mPCIUSB (35 pins), Eth (C13.1 LAN.10 LAN.S1 LAN.S2), Power (38 pins), SDCard (7 pins), Sound (HeadSet.2), Config (BOOT.1 R3.1), USBHUB2 (57 pins), UARTS (23 pins), Others (6 pins), eMod-Wifi (6 pins), CAN (5 pins)
HDMI_1V8: Display (19 pins), Power (C25.1 U6.2)
VDD_3V3: Display (R36.2 R38.1), Eth (R44.1 R45.2), Power (6 pins), SDCard (10 pins), Config (6 pins), USBHUB2 (18 pins), UARTS (5 pins), Others (PORT.37 R8.2), eMod-Wifi (eMOD1.19 Q3.2 R13.1), CAN (C35.1 R65.1 U2.3)
VDD_4G: mPCIUSB (15 pins), Power (R79.1)
VDD_5V: Display (Display.43 Display.44 Display.45 F2.2), SODIMM-2 (5 pins), Power (10 pins), USBHUB2 (F1.2 USB_HDR.1 USB_HDR.2), Others (PORT.1), eMod-Wifi (eMOD1.1)
VRTC: SODIMM-2 (CORE.198), Power (BAT.1)
AIN0: SODIMM-2 (CORE.9), Others (PORT.39)
AIN1: SODIMM-2 (CORE.5), Others (PORT.40)
AIN2: SODIMM-2 (CORE.3), Others (PORT.41)
AIN3: SODIMM-2 (CORE.7), Others (PORT.42)
AIN4: SODIMM-2 (CORE.4), Others (PORT.43)
AIN5: SODIMM-2 (CORE.6), Others (PORT.44)
AIN6: SODIMM-2 (CORE.8), Others (PORT.45)
AIN7: SODIMM-2 (CORE.10), Others (PORT.46)
CAN0_RX: SODIMM-2 (CORE.141), CAN (C34.1 U2.4)
CAN0_TX: SODIMM-2 (CORE.139), CAN (U2.1)
ETH1_LED_Act: SODIMM-2 (CORE.191), Eth (LAN.12)
ETH1_LED_SPEED: SODIMM-2 (CORE.193), Eth (LAN.14)
ETH1_MDI0_N: SODIMM-2 (CORE.175), Eth (LAN.3)
ETH1_MDI0_P: SODIMM-2 (CORE.173), Eth (LAN.2)
ETH1_MDI1_N: SODIMM-2 (CORE.179), Eth (LAN.5)
ETH1_MDI1_P: SODIMM-2 (CORE.177), Eth (LAN.4)
ETH1_MDI2_N: SODIMM-2 (CORE.183), Eth (LAN.7)
ETH1_MDI2_P: SODIMM-2 (CORE.181), Eth (LAN.6)
ETH1_MDI3_N: SODIMM-2 (CORE.187), Eth (LAN.9)
ETH1_MDI3_P: SODIMM-2 (CORE.185), Eth (LAN.8)
GPIO0_18: SODIMM-2 (CORE.163), Others (PORT.19), eMod-Wifi (R14.1)
GPIO0_19: SODIMM-2 (CORE.101), Others (PORT.20), eMod-Wifi (eMOD1.4)
GPIO0_20: SODIMM-2 (CORE.165), Others (PORT.21)
GPIO1_16: SODIMM-2 (CORE.73), Others (PORT.25)
GPIO1_17: SODIMM-2 (CORE.95), Others (PORT.26)
GPIO1_18: SODIMM-2 (CORE.81), Others (PORT.27)
GPIO1_19: SODIMM-2 (CORE.79), Others (PORT.28)
GPIO1_20: SODIMM-2 (CORE.77), Others (PORT.29)
GPIO1_21: SODIMM-2 (CORE.75), Others (PORT.30)
GPIO1_22: SODIMM-2 (CORE.83), Others (PORT.31)
GPIO1_23: SODIMM-2 (CORE.85), Others (PORT.32)
GPIO3_17: Display (Display.4), SODIMM-2 (CORE.36), Others (PORT.22)
GPIO3_18: Display (Display.5), SODIMM-2 (CORE.38), Others (PORT.23)
GPIO3_19: SODIMM-2 (CORE.117), SDCard (R4.1 SD_CARD.9)
GPIO3_21: SODIMM-2 (CORE.167), Others (PORT.24)
HP-L: SODIMM-2 (CORE.123), Sound (HeadSet.8)
HP-R: SODIMM-2 (CORE.121), Sound (HeadSet.3)
HUSB0_N: USBHUB2 (R60.1), eMod-Wifi (eMOD1.11)
HUSB0_P: USBHUB2 (R61.1), eMod-Wifi (eMOD1.9)
HUSB1_N: mPCIUSB (4G_Module.36), USBHUB2 (R53.1)
HUSB1_P: mPCIUSB (4G_Module.38), USBHUB2 (R54.1)
HUSB4_N: Display (Display.8), USBHUB2 (R110.1)
HUSB4_P: Display (Display.7), USBHUB2 (R111.1)
HUSB5_N: USBHUB2 (R96.1), eMod-Wifi (U11.2)
HUSB5_P: USBHUB2 (R97.1), eMod-Wifi (U11.3)
I2C0_SCL: Display (Display.2 Display.3 U1.51 U1.52), SODIMM-2 (CORE.18 CORE.20)
I2C1_SCL: SODIMM-2 (CORE.157), Others (PORT.18), eMod-Wifi (eMOD1.15)
I2C1_SDA: SODIMM-2 (CORE.155), Others (PORT.17), eMod-Wifi (eMOD1.17)
LCD_DATA0: Display (RN2.4 U1.60), SODIMM-2 (CORE.27)
LCD_DATA1: Display (RN1.1 U1.59), SODIMM-2 (CORE.25)
LCD_DATA2: Display (RN1.2 U1.58), SODIMM-2 (CORE.23), Config (R1.2 R10.2)
LCD_DATA3: Display (RN1.3 U1.57), SODIMM-2 (CORE.21), Config (R2.2 R3.2 R9.2)
LCD_DATA4: Display (RN1.4 U1.56), SODIMM-2 (CORE.19), Config (R7.2)
LCD_DATA5: Display (RN4.3 U1.7), SODIMM-2 (CORE.47), Config (R11.2)
LCD_DATA6: Display (RN4.4 U1.6), SODIMM-2 (CORE.45)
LCD_DATA7: Display (RN3.1 U1.3), SODIMM-2 (CORE.43)
LCD_DATA8: Display (RN3.2 U1.2), SODIMM-2 (CORE.41)
LCD_DATA9: Display (RN3.3 U1.1), SODIMM-2 (CORE.39)
LCD_DATA10: Display (RN3.4 U1.64), SODIMM-2 (CORE.37)
LCD_DATA11: Display (RN6.4 U1.15), SODIMM-2 (CORE.63)
LCD_DATA12: Display (RN5.1 U1.13), SODIMM-2 (CORE.61)
LCD_DATA13: Display (RN5.2 U1.12), SODIMM-2 (CORE.59)
LCD_DATA14: Display (RN5.3 U1.11), SODIMM-2 (CORE.57), Config (R12.2)
LCD_DATA15: Display (RN5.4 U1.10), SODIMM-2 (CORE.55)
LCD_DATA16: Display (RN2.3 U1.61), SODIMM-2 (CORE.29)
LCD_DATA17: Display (RN6.3 U1.16), SODIMM-2 (CORE.65)
LCD_DATA18: Display (RN2.2 U1.62), SODIMM-2 (CORE.31)
LCD_DATA19: Display (RN4.2 U1.8), SODIMM-2 (CORE.49)
LCD_DATA20: Display (RN6.2 U1.17), SODIMM-2 (CORE.67)
LCD_DATA21: Display (RN2.1 U1.63), SODIMM-2 (CORE.33)
LCD_DATA22: Display (RN4.1 U1.9), SODIMM-2 (CORE.51)
LCD_DATA23: Display (RN6.1 U1.18), SODIMM-2 (CORE.69)
LCD_DE: Display (RN7.8 U1.20), SODIMM-2 (CORE.70)
LCD_EN: Display (Display.1), SODIMM-2 (CORE.72)
LCD_HSYNC: Display (RN7.6 U1.22), SODIMM-2 (CORE.66)
LCD_PCLK: Display (RN7.5 U1.4), SODIMM-2 (CORE.64)
LCD_SIG_H.LCD_VSYNC: Display (RN7.7 U1.21), SODIMM-2 (CORE.68)
McASP0_ACLKX: Display (U1.23), SODIMM-2 (CORE.87), Others (PORT.33)
McASP0_AXR0: Display (U1.25), SODIMM-2 (CORE.91), Others (PORT.35)
McASP0_AXR1: Display (U1.26), SODIMM-2 (CORE.93), Others (PORT.36)
McASP0_FSX: Display (U1.24), SODIMM-2 (CORE.89), Others (PORT.34)
MIC: SODIMM-2 (CORE.135), Sound (HeadSet.1)
MMC0_CLK: SODIMM-2 (CORE.111), SDCard (R90.1 SD_CARD.5)
MMC0_CMD: SODIMM-2 (CORE.109), SDCard (R89.1 SD_CARD.3)
MMC0_D0: SODIMM-2 (CORE.113), SDCard (R91.1 SD_CARD.7)
MMC0_D1: SODIMM-2 (CORE.115), SDCard (R92.1 SD_CARD.8)
MMC0_D2: SODIMM-2 (CORE.105), SDCard (R87.1 SD_CARD.1)
MMC0_D3: SODIMM-2 (CORE.107), SDCard (R88.1 SD_CARD.2)
RESETOUTn: SODIMM-2 (CORE.192), mPCIUSB (R49.2), USBHUB2 (C70.1 C89.1 U10.26 U12.26), Others (PORT.3 R8.1 RST.1), eMod-Wifi (eMOD1.2)
SPI1_CS0_/_UART5_TXD: SODIMM-2 (CORE.80), Others (PORT.13), eMod-Wifi (eMOD1.16)
SPI1_D0_/_UART5_CTSN: SODIMM-2 (CORE.78), Others (PORT.15), eMod-Wifi (eMOD1.20)
SPI1_D1_/_UART5_RTSN: SODIMM-2 (CORE.74), Others (PORT.16), eMod-Wifi (eMOD1.18)
SPI1_SCLK_/_UART5_RXD: SODIMM-2 (CORE.76), Others (PORT.14), eMod-Wifi (eMOD1.14)
UART0_RXD: SODIMM-2 (CORE.28), UARTS (U8.21)
UART0_TXD: SODIMM-2 (CORE.30), UARTS (U8.20)
UART1_RXD: SODIMM-2 (CORE.145), UARTS (U7.9), Others (PORT.6)
UART1_TXD: SODIMM-2 (CORE.143), UARTS (U7.10), Others (PORT.5)
UART2_RXD: SODIMM-2 (CORE.153), UARTS (P1.1), Others (PORT.8)
UART2_TXD: SODIMM-2 (CORE.151), UARTS (R19.2 R100.1), Others (PORT.7)
UART3_RXD: SODIMM-2 (CORE.149), Others (PORT.10), eMod-Wifi (eMOD1.3)
UART3_TXD: SODIMM-2 (CORE.147), Others (PORT.9), eMod-Wifi (eMOD1.5)
UART4_RXD: SODIMM-2 (CORE.24), Others (PORT.12)
UART4_TXD: SODIMM-2 (CORE.26), Others (PORT.11)
USB0_D_N: SODIMM-2 (CORE.48), USBHUB2 (U12.3)
USB0_D_P: SODIMM-2 (CORE.46), USBHUB2 (U12.4)
USB0_ID: SODIMM-2 (CORE.44), USBHUB2 (R40.1)
USB1_D_N: SODIMM-2 (CORE.58), USBHUB2 (U10.3)
USB1_D_P: SODIMM-2 (CORE.56), USBHUB2 (U10.4)
USB1_ID: SODIMM-2 (CORE.54), USBHUB2 (R153.1)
